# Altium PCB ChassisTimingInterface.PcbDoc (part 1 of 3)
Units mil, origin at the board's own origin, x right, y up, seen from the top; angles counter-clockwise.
Board outline 3400 x 6000 mil, 8 copper layers (Top Layer, GND, VDD, Mid-Layer 1, VCCAUX, Mid-Layer 2, MidLayer3, Bottom Layer), stack 62.1 mil thick; 229 components, 254 nets, 1249 pads, 708 vias.
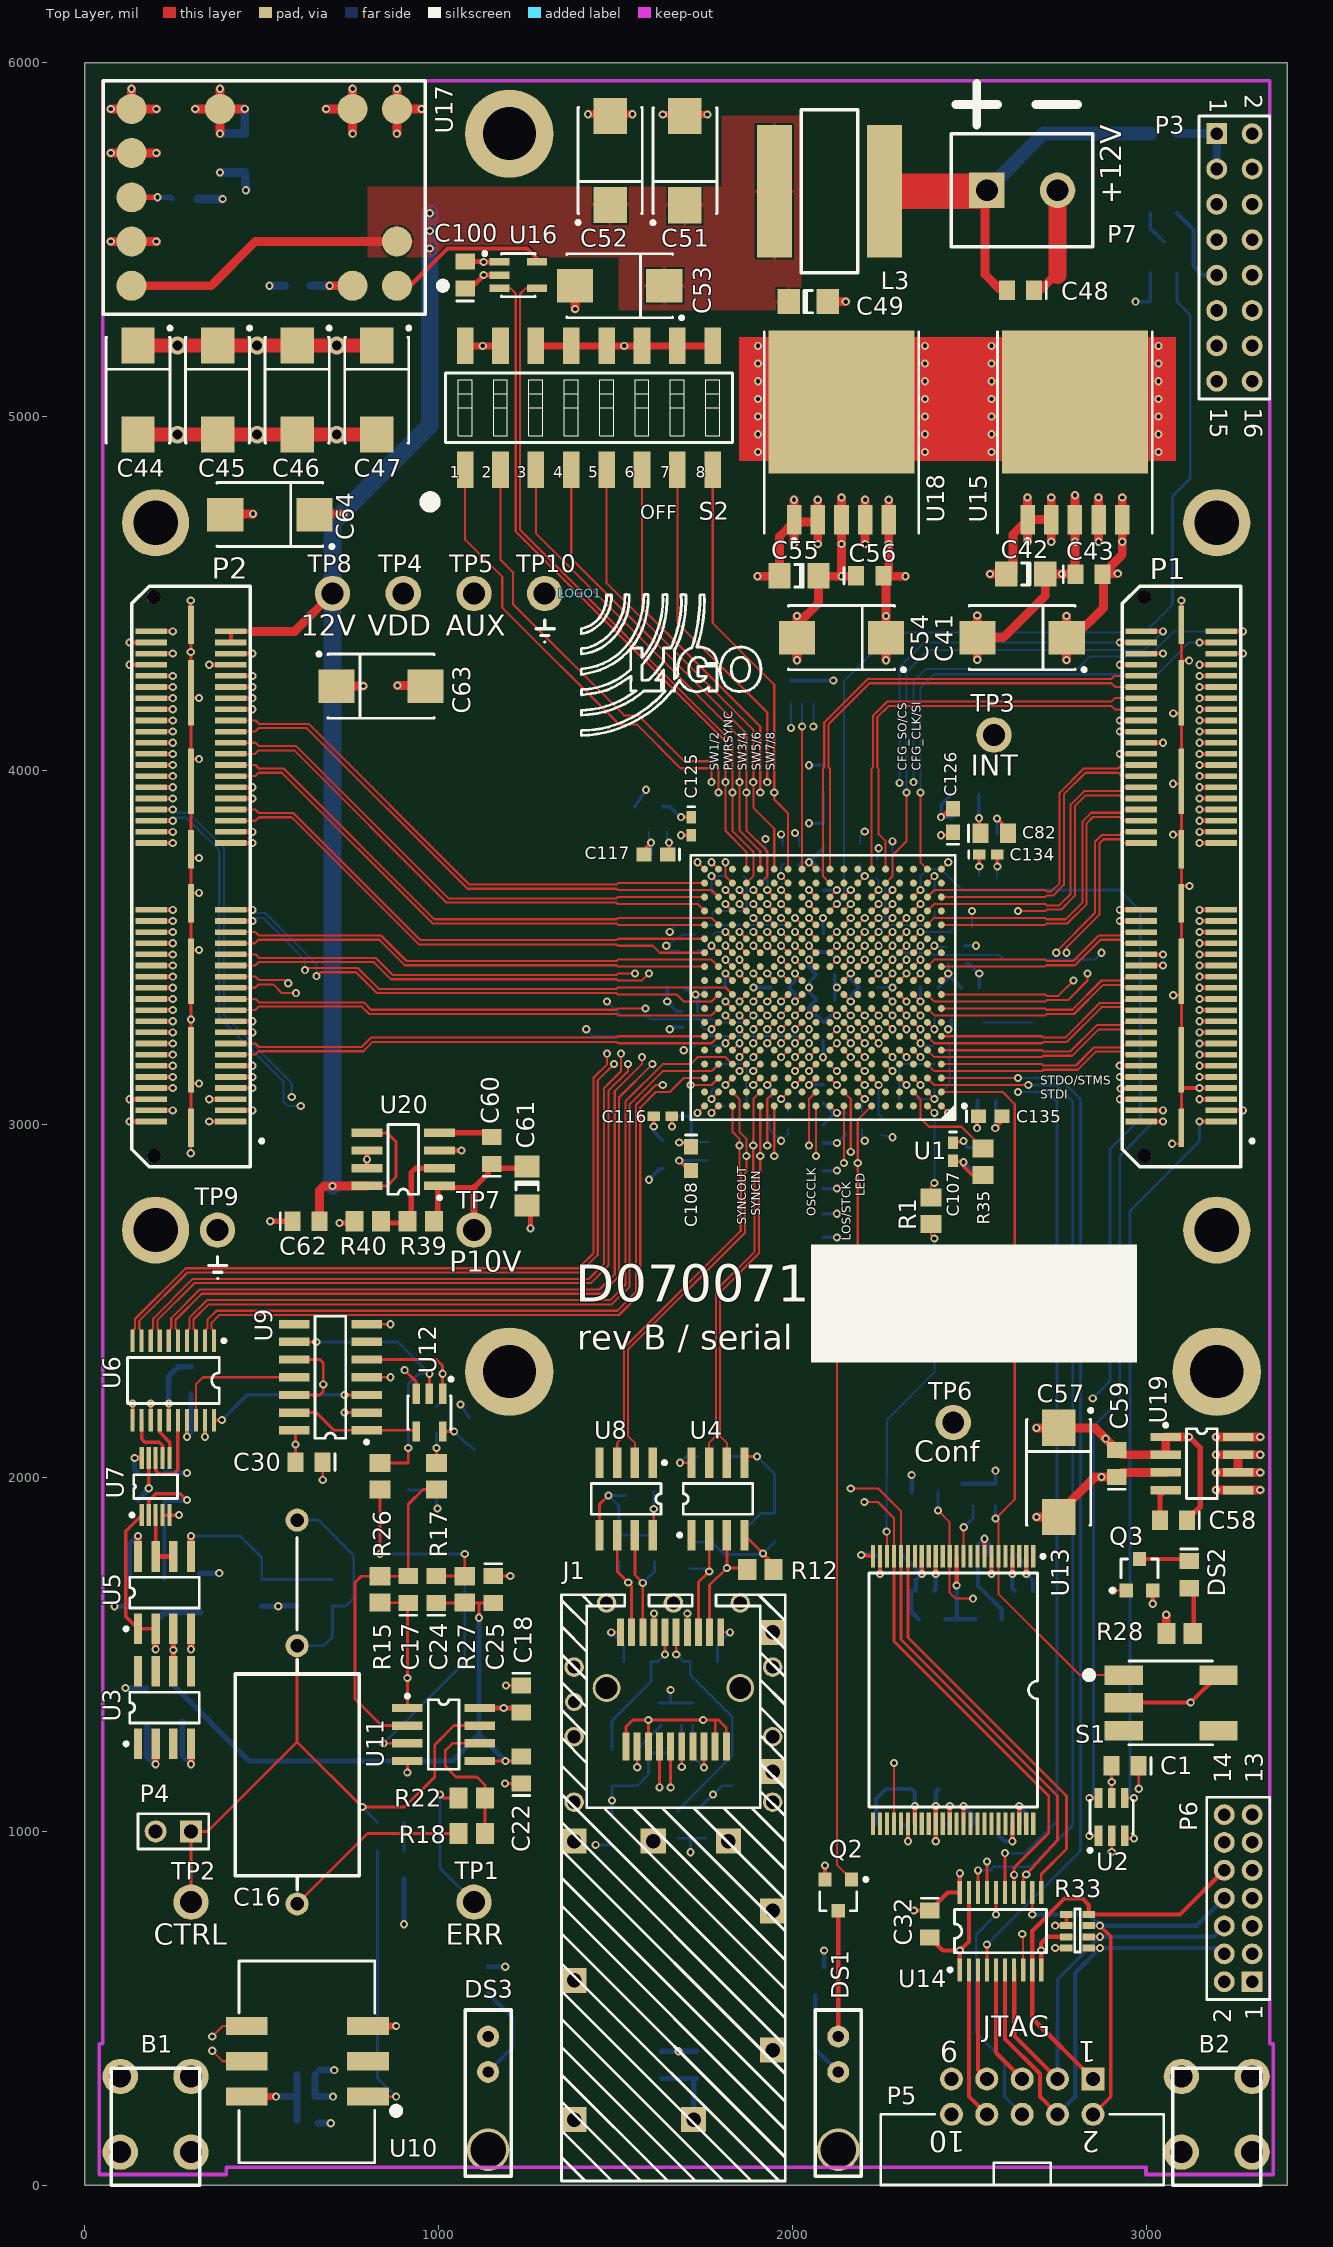
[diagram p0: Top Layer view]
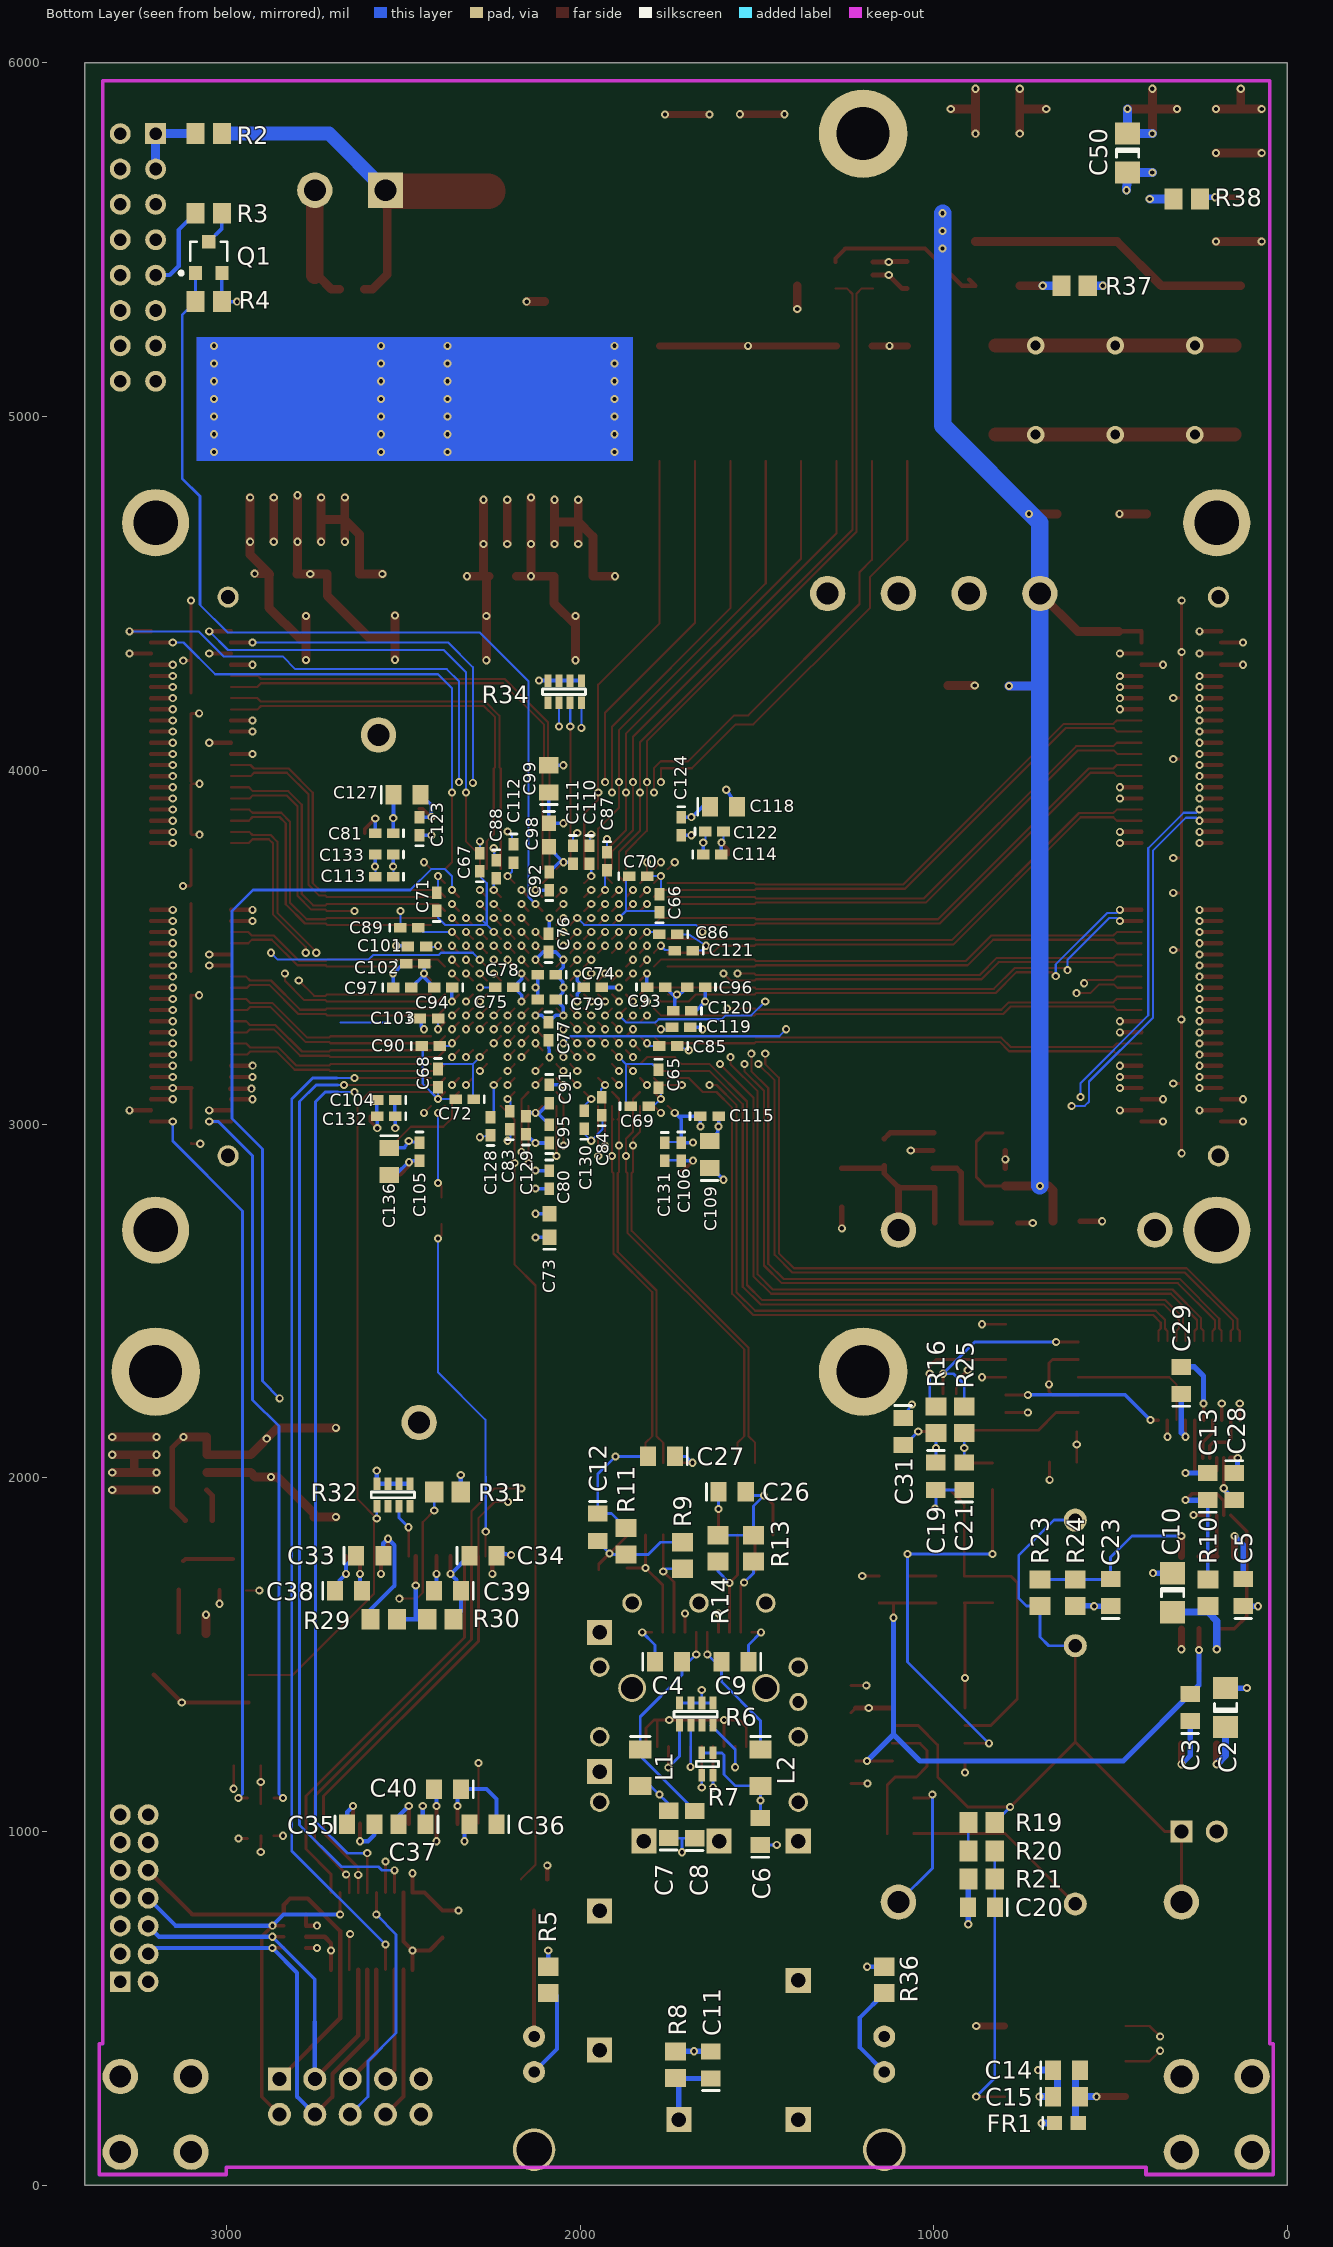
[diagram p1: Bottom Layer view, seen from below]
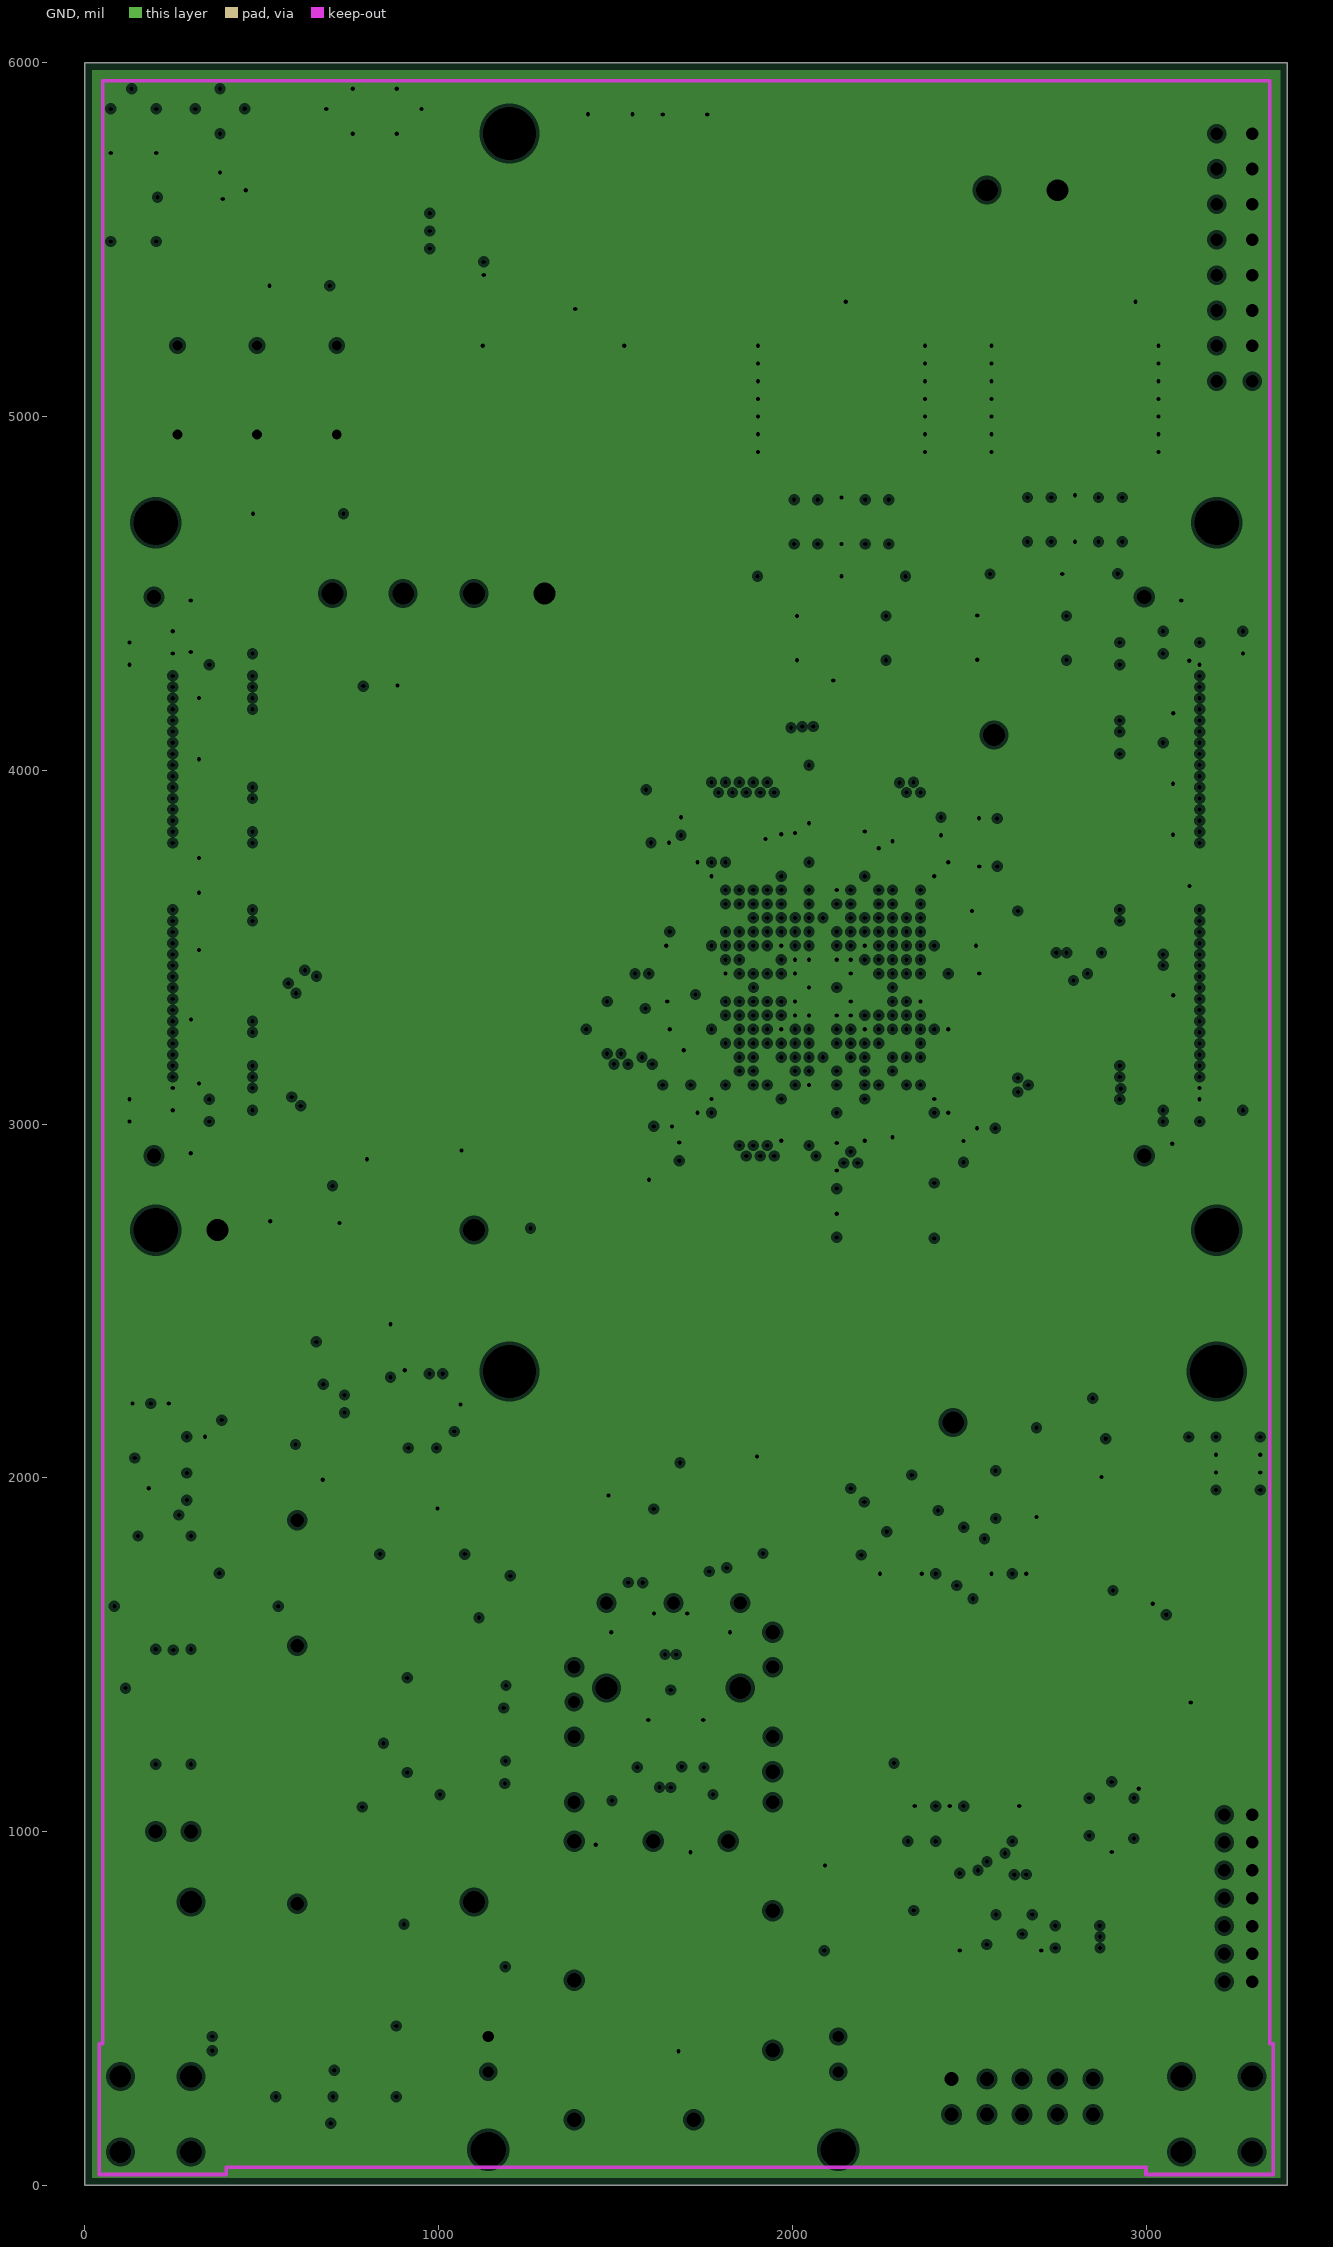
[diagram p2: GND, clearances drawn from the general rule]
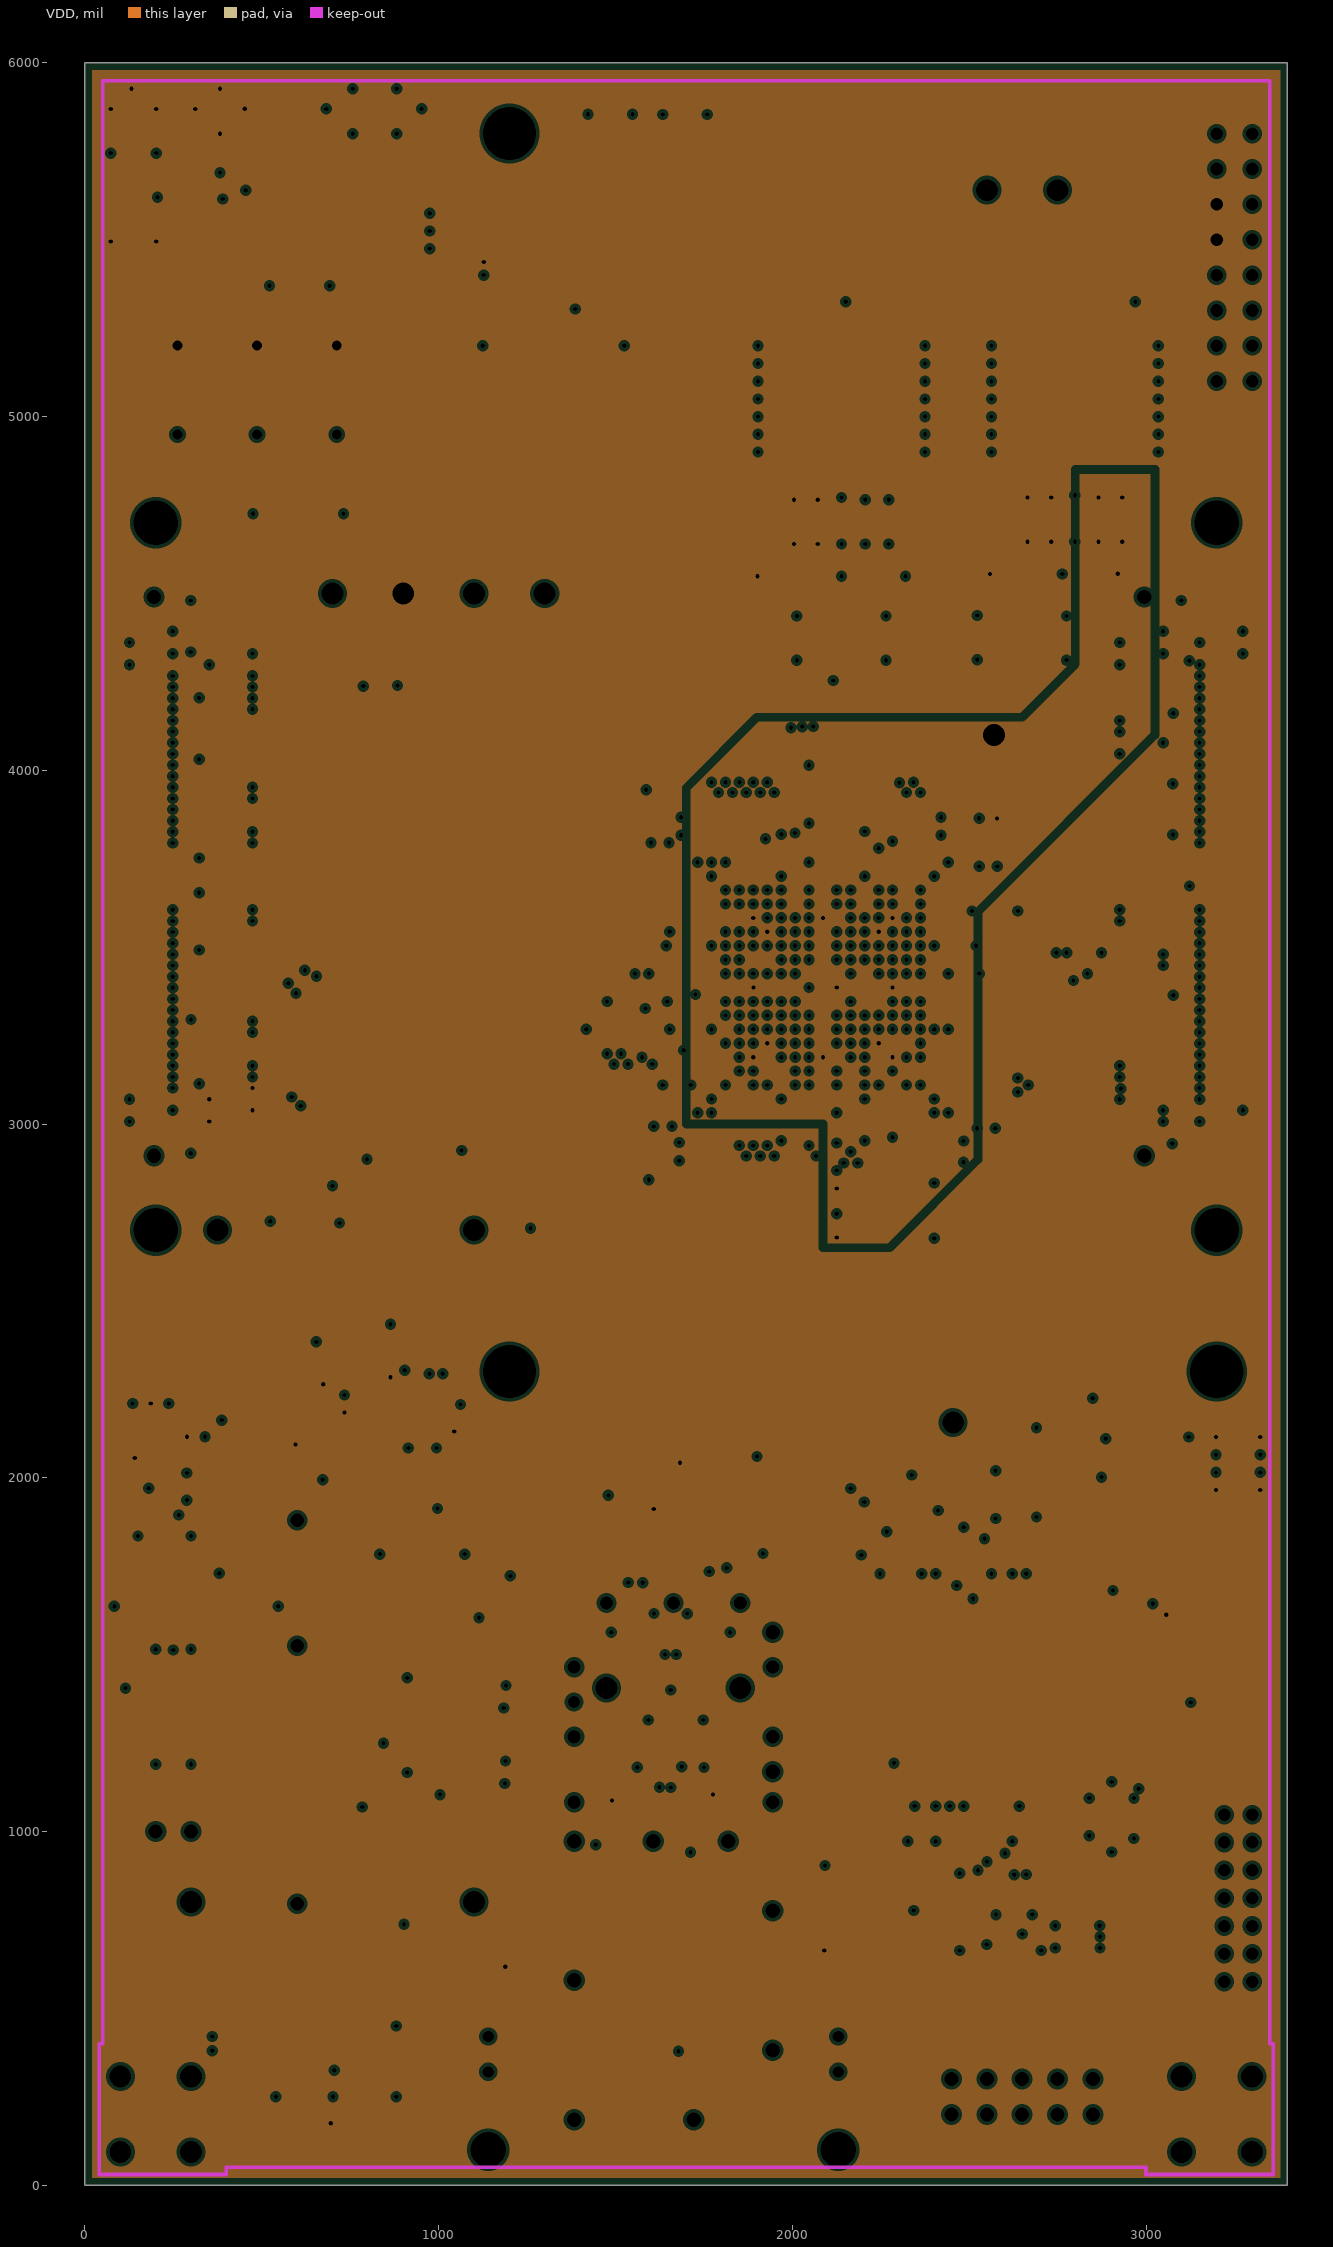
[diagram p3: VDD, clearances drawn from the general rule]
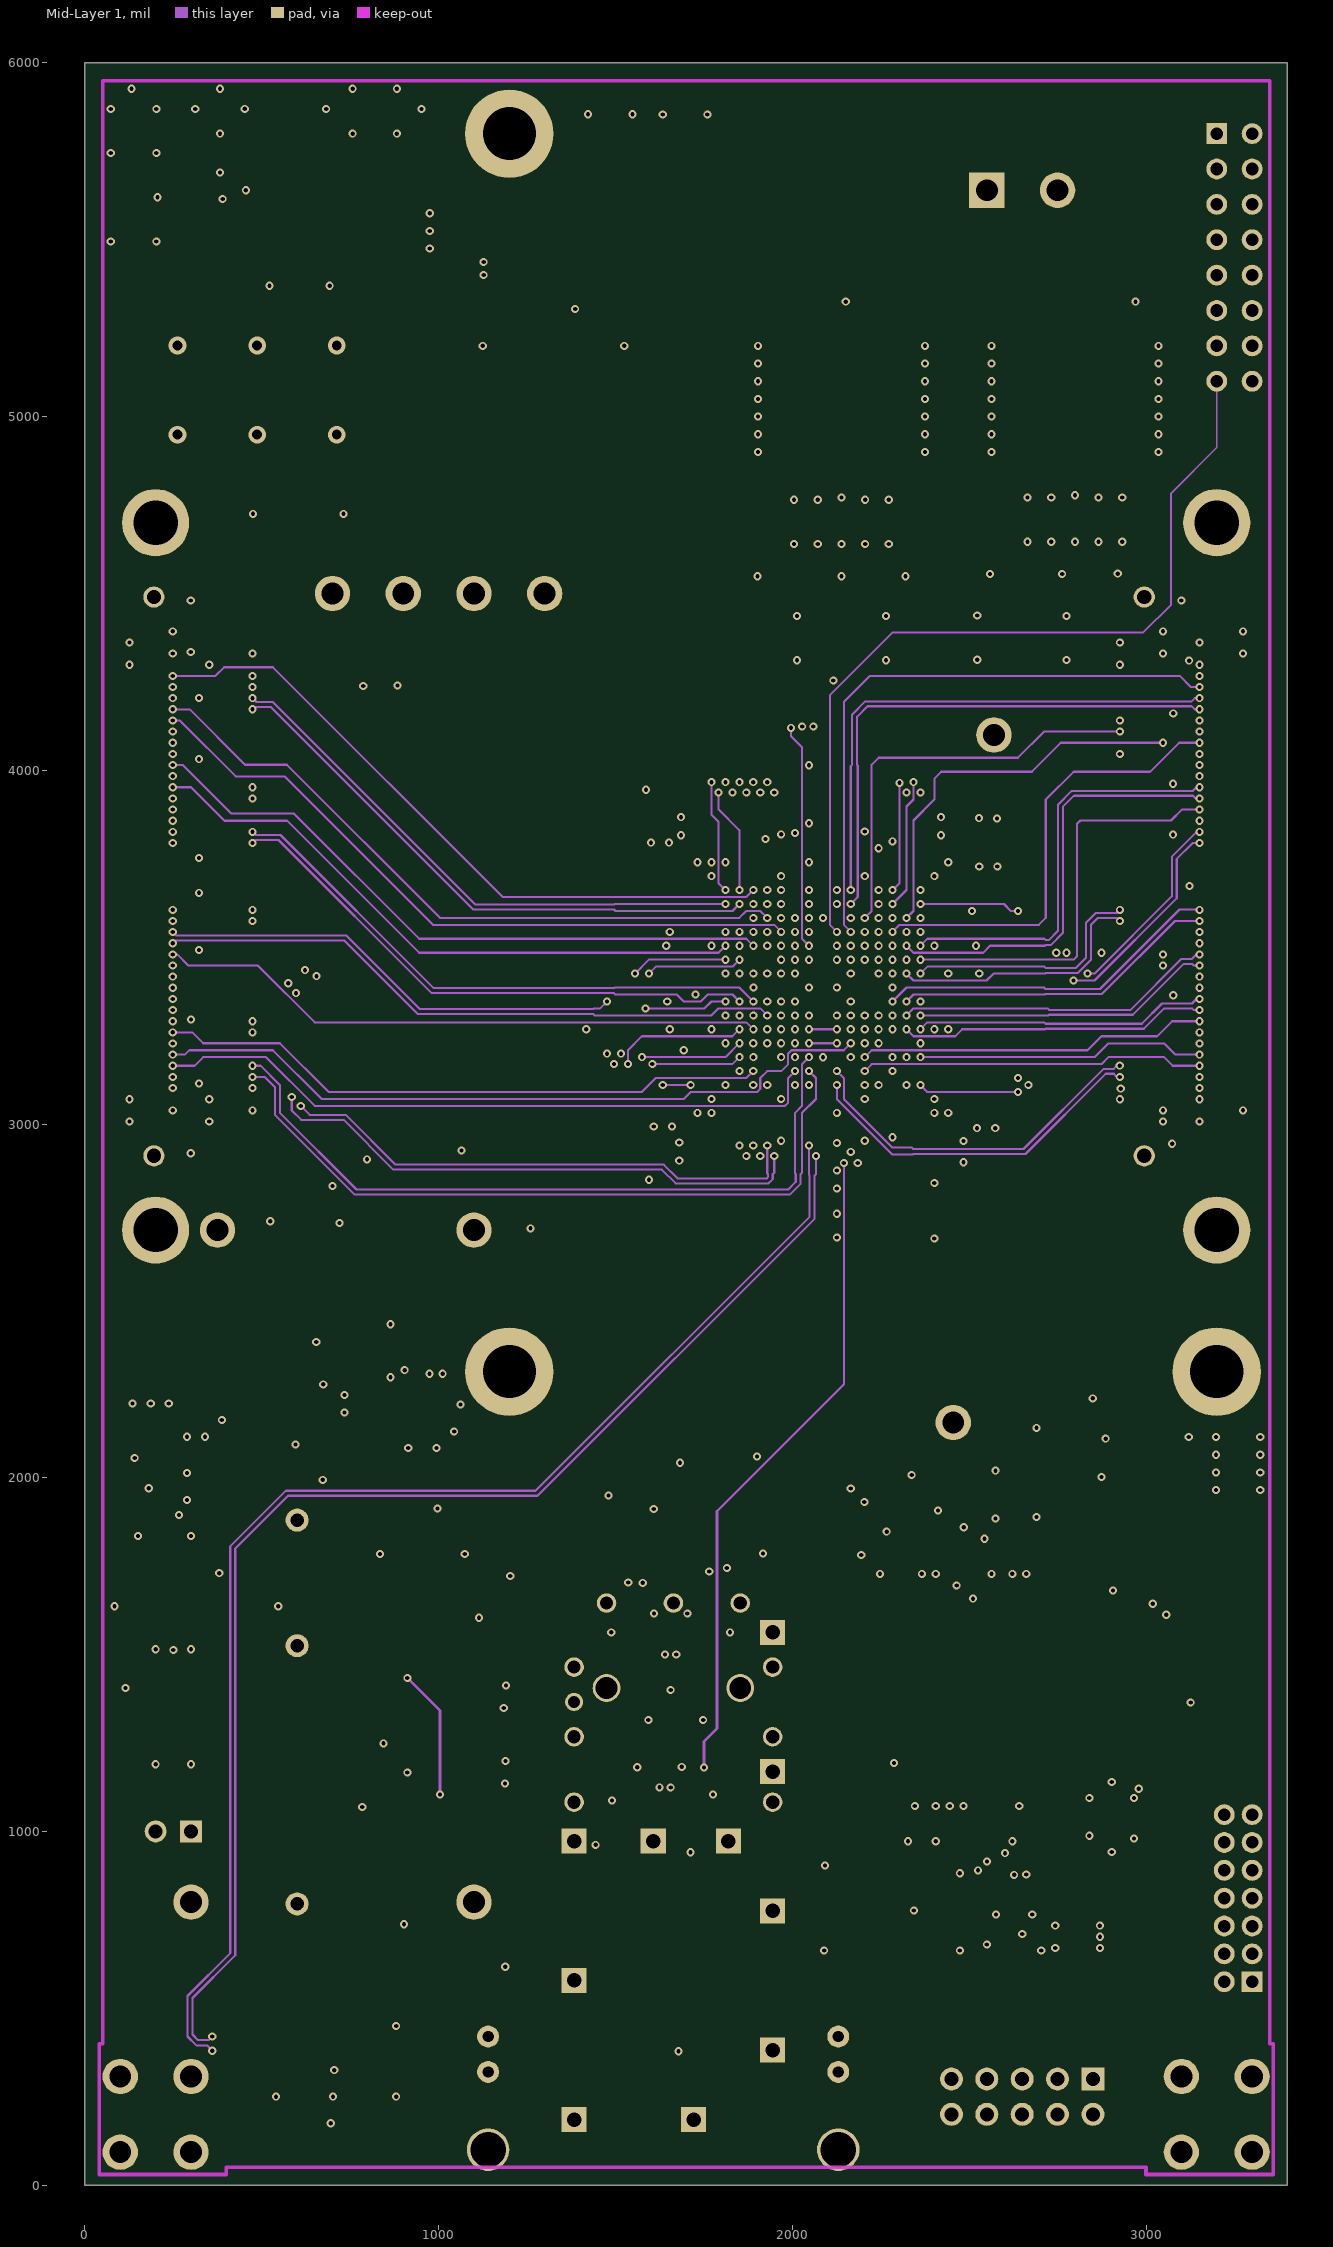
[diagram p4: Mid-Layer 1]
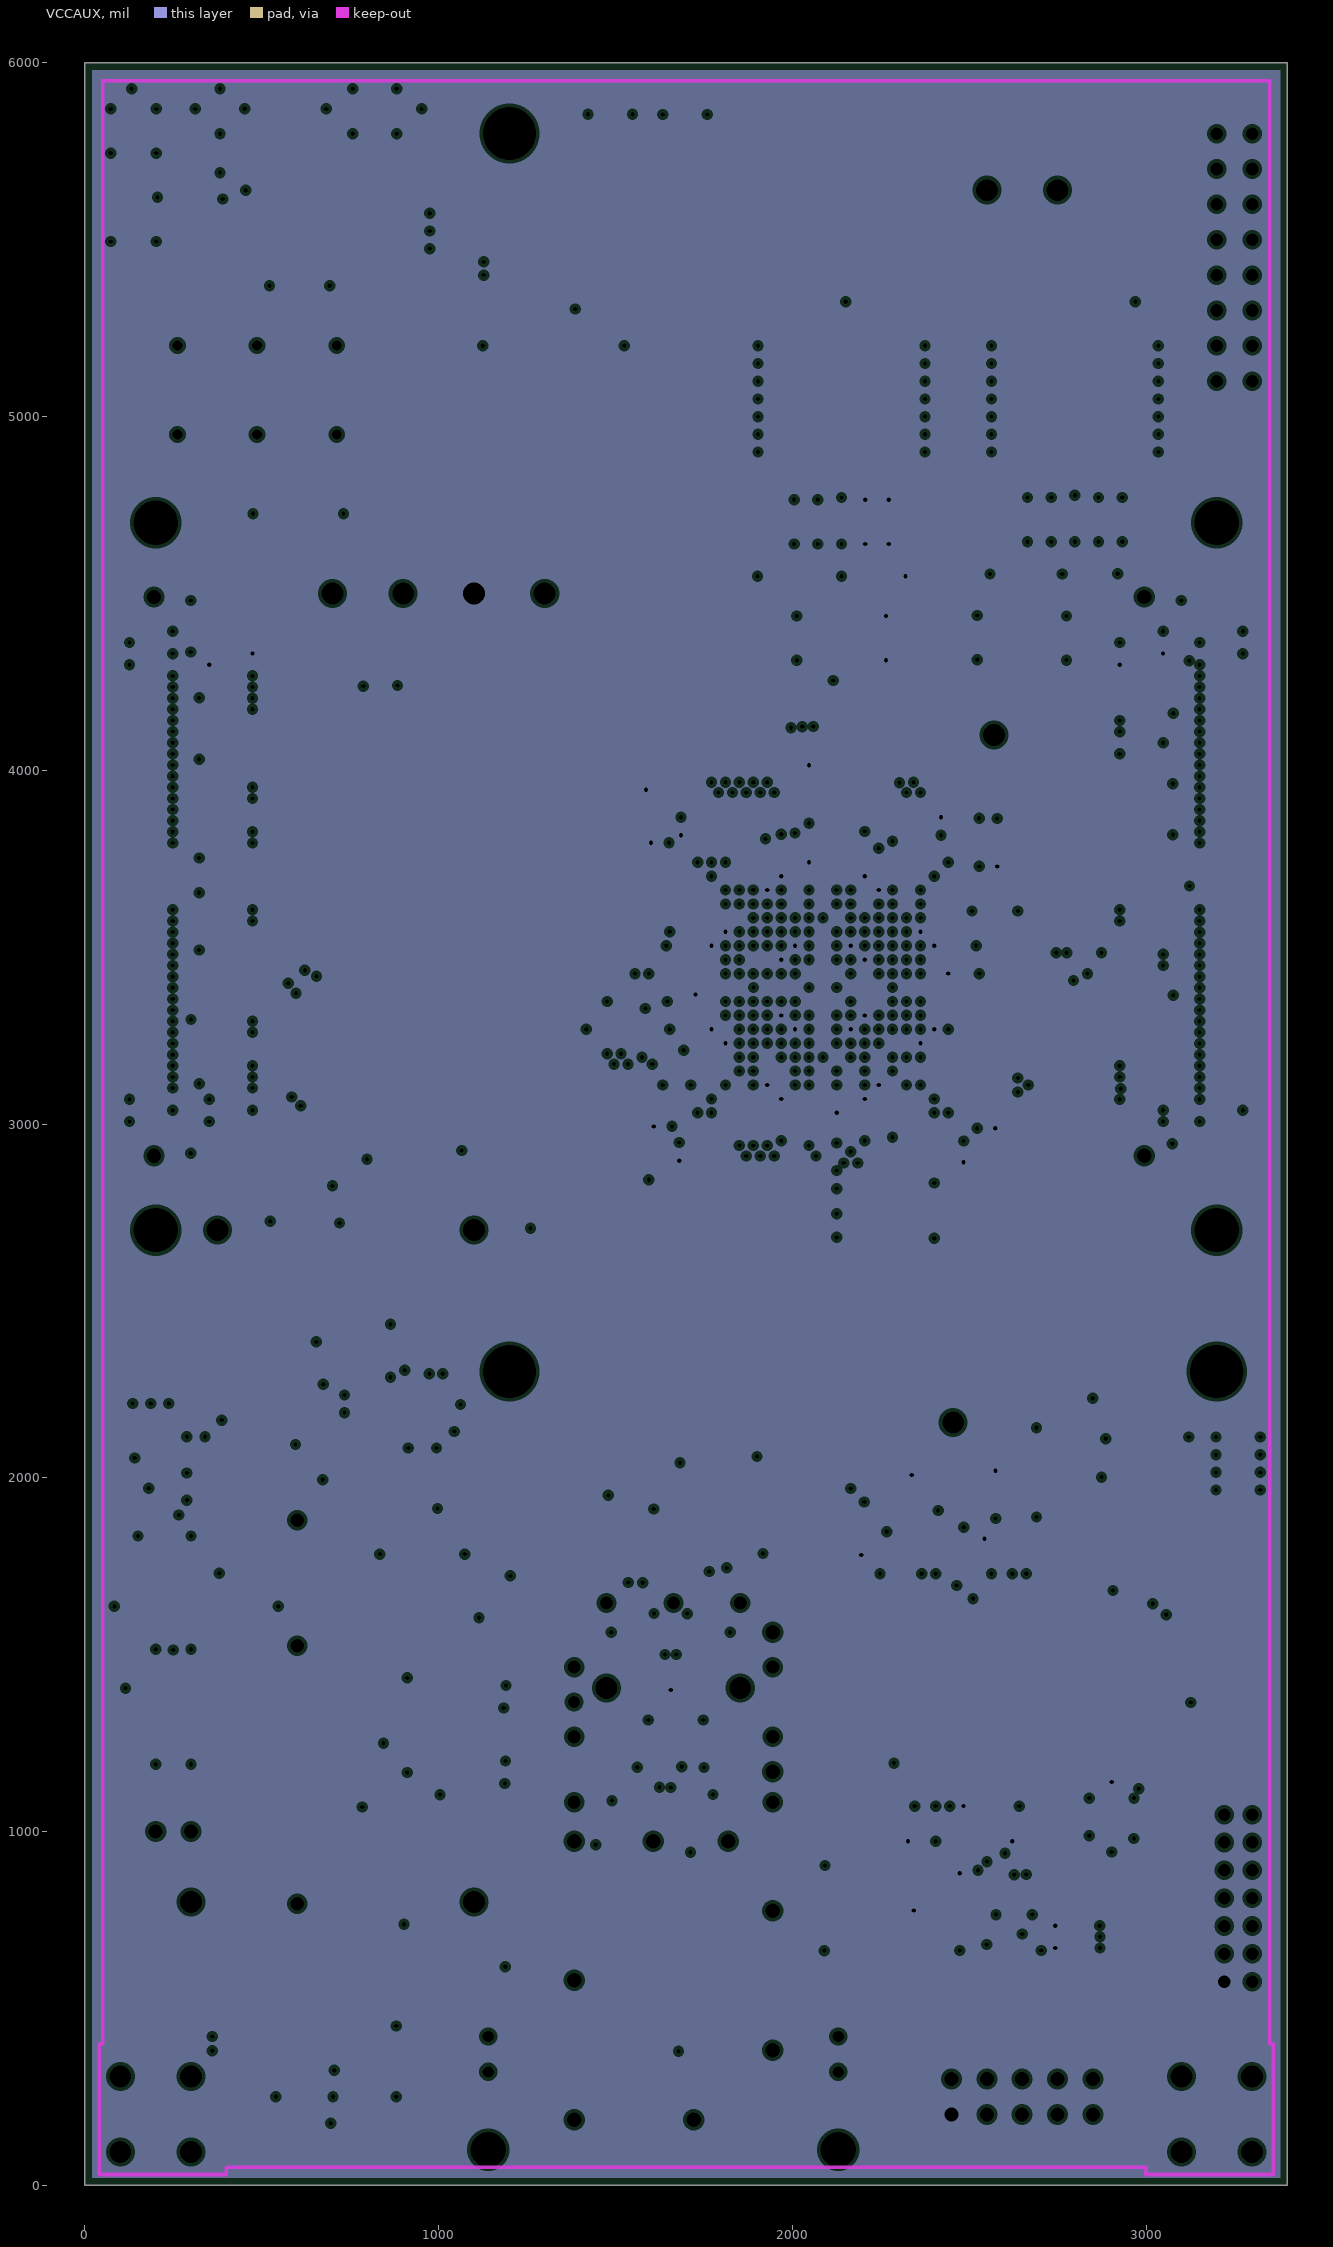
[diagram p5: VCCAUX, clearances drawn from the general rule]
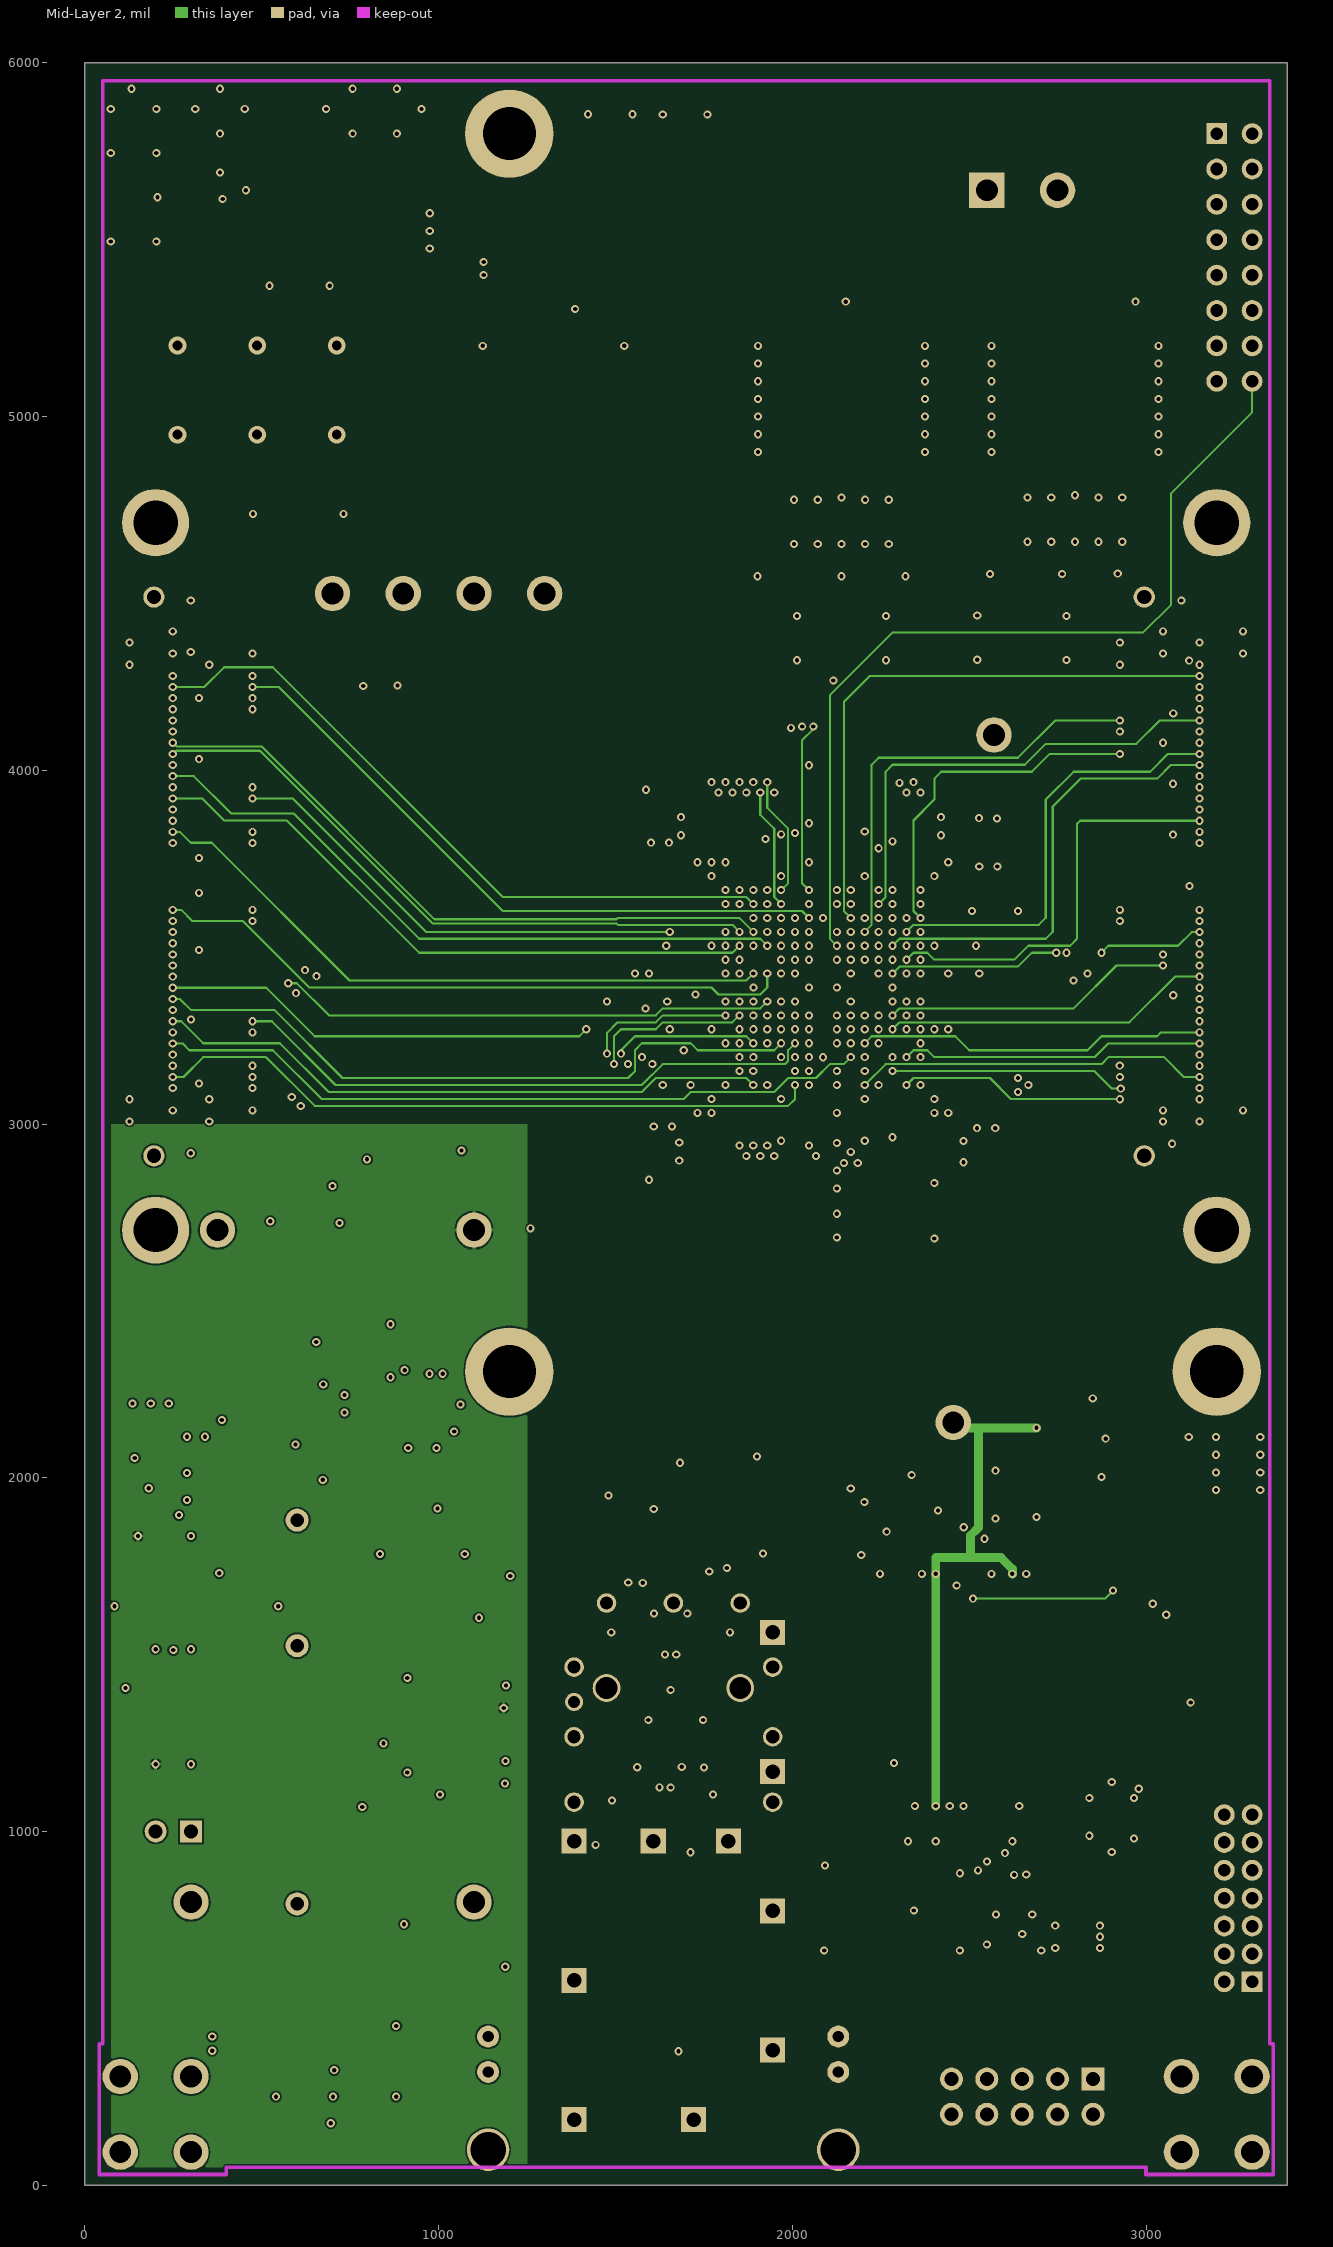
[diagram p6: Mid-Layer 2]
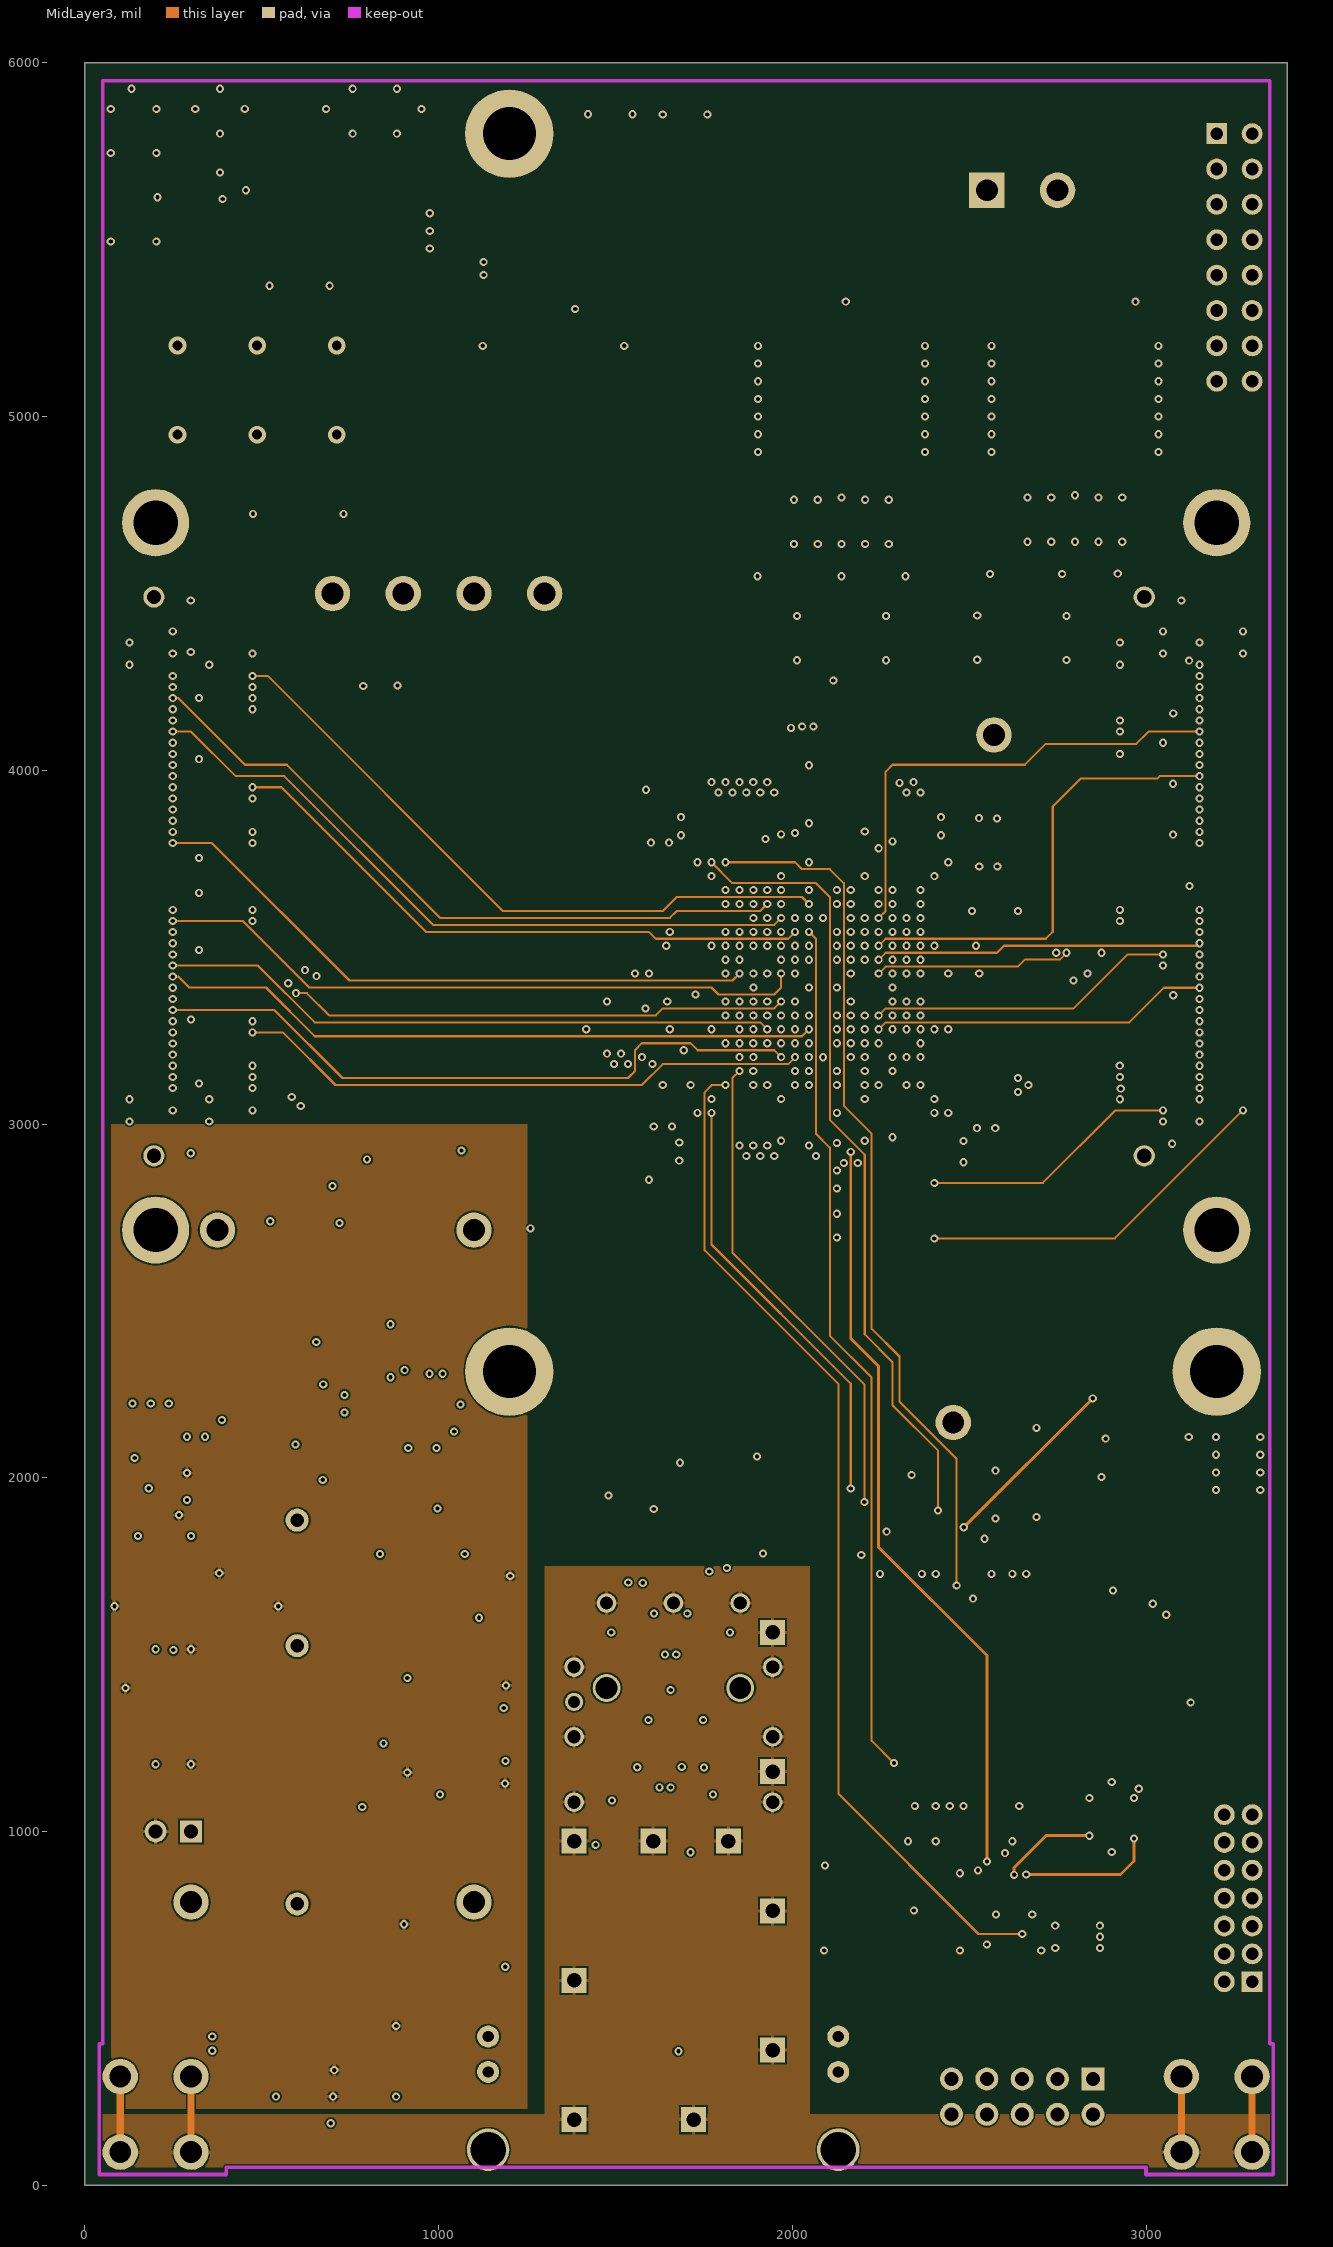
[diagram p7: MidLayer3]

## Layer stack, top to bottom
Top Layer: signal copper 1.4
Dielectric: prepreg 5.6, FR-4, Dk 4.2
GND: plane copper 1.4, net GND
Dielectric: core 9.5, FR-4, Dk 4.2
VDD: plane copper 1.4, net (Multiple Nets)
Dielectric: prepreg 5.6, FR-4, Dk 4.2
Mid-Layer 1: signal copper 1.4
Dielectric: core 9.5, FR-4, Dk 4.2
VCCAUX: plane copper 1.4, net VCCAUX
Dielectric: prepreg 5.6, FR-4, Dk 4.2
Mid-Layer 2: signal copper 1.4
Dielectric: core 9.5, FR-4, Dk 4.2
MidLayer3: signal copper 1.4
Dielectric: prepreg 5.6, FR-4, Dk 4.2
Bottom Layer: signal copper 1.4

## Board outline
0,0 0,6000 3400,6000 3400,0

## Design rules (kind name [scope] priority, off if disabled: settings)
Clearance Clearance_1 [All] p1: gap=5
ComponentClearance ComponentClearance_B2P4 [(InComponent('B2')) vs (InComponent('P5'))] p1: gap=-25 collisioncheckmode=0 verticalgap=25
ComponentClearance [All] p2: gap=10 collisioncheckmode=3 verticalgap=10
DiffPairsRouting [All] p1: maxlimit=10 minlimit=6 mostfreqgap=10 toplayer_prefgap=6 midlayer1_mingap=8 midlayer1_prefgap=8 midlayer2_prefgap=6 midlayer3_prefgap=6 bottomlayer_mingap=10 maxuncoupledlength=500
HoleSize [All] p1: absolutevalues=TRUE maxlimit=250 minlimit=1 maxpercent=80.000 minpercent=20.000
PlaneClearance [All] p1: clearance=10
PlaneConnect [All] p1: planeconnectstyle=Relief reliefexpansion=10 reliefentries=4 reliefconductorwidth=10 reliefairgap=10
PolygonConnect [All] p1: connectstyle=Relief reliefconductorwidth=10 reliefentries=4 polygonreliefangle="90 Angle"
RoomDefinition FPGA [InComponentClass('FPGA')] p1: confinementstyle=ConfineIn formatcopy=TRUE lockcomponents=FALSE outline -2000,-3000 0,-3000 0,-2000 -2000,-2000
RoutingLayers [All] p1: top layer_v5=TRUE mid layer 1_v5=TRUE mid layer 2_v5=TRUE mid layer 3_v5=FALSE bottom layer_v5=TRUE
RoutingVias [All] p1: holewidth=12 width=23 viastyle="Through Hole" minholewidth=12 minwidth=23 maxholewidth=28 maxwidth=50
ShortCircuit AGND [InNet('AGND') vs InNet('GND')] p1: allowed=TRUE
ShortCircuit [All] p2: allowed=FALSE
SolderMaskExpansion [All] p1: expansion=4
TestPointUsage [All] p1: valid=0 allowmultiple=FALSE
Testpoint [All] p1: side=15 testpointundercomponent=TRUE minsize=40 maxsize=100 preferedsize=60 minholesize=0 maxholesize=40 preferedholesize=32 testpointgrid=1 style=1023 order=0-112345678
Width [All] p1: maxlimit=100 minlimit=5 preferedwidth=5
12 further rules are at their usual default settings.

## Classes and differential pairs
component class FPGA: U1_B
component class ChassisTimingInterface1: C1 H1 H2 H3 H4 H5 H6 H7 H8 H9 H10 H11 H12 H13 H14 H15 H16 H17 H18 H19 H20 LOGO1 P1 P2 P3 Q1 R1 R2 R3 R4 U2
net class SW[10..1]: SW1 SW2 SW3 SW4 SW5 SW6 SW7 SW8 SW9 SW10
component class FIB: B1 B2 C2 C3 C4 C5 C6 C7 C8 C9 C10 C11 C12 C13 C14 C15 C16 C17 C18 C19 C20 C21 C22 C23 C24 C25 C26 C27 C28 C29 C30 C31 DS1 FR1 J1 L1 L2 LOGO2 P4 Q2 R5 R6 R7 R8 R9 R10 R11 R12 R13 R14 R15 R16 R17 R18 R19 R20 R21 R22 R23 R24 R25 R26 R27 TP1 TP2 U3 U4 U5 U6 U7 U8 U9 U10 U11 U12
component class PRG: C32 C33 C34 C35 C36 C37 C38 C39 C40 DS2 LOGO3 P5 P6 Q3 R28 R29 R30 R31 R32 R33 R34 R35 S1 S2 U13 U14
component class PWR: C41 C42 C43 C44 C45 C46 C47 C48 C49 C50 C51 C52 C53 C54 C55 C56 C57 C58 C59 C60 C61 C62 C63 C64 C65 C66 C67 C68 C69 C70 C71 C72 C73 C74 C75 C76 C77 C78 C79 C80 C81 C82 C83 C84 C85 C86 C87 C88 C89 C90 C91 C92 C93 C94 C95 C96 C97 C98 C99 C100 C101 C102 C103 C104 C105 C106 C107 C108 C109 C110 C111 C112 C113 C114 C115 C116 C117 C118 C119 C120 C121 C122 C123 C124 C125 C126 C127 C128 C129 C130 C131 C132 C133 C134 C135 C136 C194 DS3 L3 LOGO4 P7 R36 R37 R38 R39 R40 TP3 TP4 TP5 TP6 TP7 TP8 TP9 TP10 U15 U16 U17 U18 U19 U20
component class U_FPGA_U1_Auto: U1
differential pair S49_64.S64: +S49_64.S64_P -S49_64.S64_N
differential pair S49_64.S63: +S49_64.S63_P -S49_64.S63_N
differential pair S49_64.S62: +S49_64.S62_P -S49_64.S62_N
differential pair S49_64.S61: +S49_64.S61_P -S49_64.S61_N
differential pair S49_64.S60: +S49_64.S60_P -S49_64.S60_N
differential pair S49_64.S59: +S49_64.S59_P -S49_64.S59_N
differential pair S49_64.S58: +S49_64.S58_P -S49_64.S58_N
differential pair S49_64.S57: +S49_64.S57_P -S49_64.S57_N
differential pair S49_64.S56: +S49_64.S56_P -S49_64.S56_N
differential pair S49_64.S55: +S49_64.S55_P -S49_64.S55_N
differential pair S49_64.S54: +S49_64.S54_P -S49_64.S54_N
differential pair S49_64.S53: +S49_64.S53_P -S49_64.S53_N
differential pair S49_64.S52: +S49_64.S52_P -S49_64.S52_N
differential pair S49_64.S51: +S49_64.S51_P -S49_64.S51_N
differential pair S49_64.S50: +S49_64.S50_P -S49_64.S50_N
differential pair S49_64.S49: +S49_64.S49_P -S49_64.S49_N
differential pair S33_48.S48: +S33_48.S48_P -S33_48.S48_N
differential pair S33_48.S47: +S33_48.S47_P -S33_48.S47_N
differential pair S33_48.S46: +S33_48.S46_P -S33_48.S46_N
differential pair S33_48.S45: +S33_48.S45_P -S33_48.S45_N
differential pair S33_48.S44: +S33_48.S44_P -S33_48.S44_N
differential pair S33_48.S43: +S33_48.S43_P -S33_48.S43_N
differential pair S33_48.S42: +S33_48.S42_P -S33_48.S42_N
differential pair S33_48.S41: +S33_48.S41_P -S33_48.S41_N
differential pair S33_48.S40: +S33_48.S40_P -S33_48.S40_N
differential pair S33_48.S39: +S33_48.S39_P -S33_48.S39_N
differential pair S33_48.S38: +S33_48.S38_P -S33_48.S38_N
differential pair S33_48.S37: +S33_48.S37_P -S33_48.S37_N
differential pair S33_48.S36: +S33_48.S36_P -S33_48.S36_N
differential pair S33_48.S35: +S33_48.S35_P -S33_48.S35_N
differential pair S33_48.S34: +S33_48.S34_P -S33_48.S34_N
differential pair S33_48.S33: +S33_48.S33_P -S33_48.S33_N
differential pair S17_32.S32: +S17_32.S32_P -S17_32.S32_N
differential pair S17_32.S31: +S17_32.S31_P -S17_32.S31_N
differential pair S17_32.S30: +S17_32.S30_P -S17_32.S30_N
differential pair S17_32.S29: +S17_32.S29_P -S17_32.S29_N
differential pair S17_32.S28: +S17_32.S28_P -S17_32.S28_N
differential pair S17_32.S27: +S17_32.S27_P -S17_32.S27_N
differential pair S17_32.S26: +S17_32.S26_P -S17_32.S26_N
differential pair S17_32.S25: +S17_32.S25_P -S17_32.S25_N
differential pair S17_32.S24: +S17_32.S24_P -S17_32.S24_N
differential pair S17_32.S23: +S17_32.S23_P -S17_32.S23_N
differential pair S17_32.S22: +S17_32.S22_P -S17_32.S22_N
differential pair S17_32.S21: +S17_32.S21_P -S17_32.S21_N
differential pair S17_32.S20: +S17_32.S20_P -S17_32.S20_N
differential pair S17_32.S19: +S17_32.S19_P -S17_32.S19_N
differential pair S17_32.S18: +S17_32.S18_P -S17_32.S18_N
differential pair S17_32.S17: +S17_32.S17_P -S17_32.S17_N
differential pair S1_16.S16: +S1_16.S16_P -S1_16.S16_N
differential pair S1_16.S15: +S1_16.S15_P -S1_16.S15_N
differential pair S1_16.S14: +S1_16.S14_P -S1_16.S14_N
differential pair S1_16.S13: +S1_16.S13_P -S1_16.S13_N
differential pair S1_16.S12: +S1_16.S12_P -S1_16.S12_N
differential pair S1_16.S11: +S1_16.S11_P -S1_16.S11_N
differential pair S1_16.S10: +S1_16.S10_P -S1_16.S10_N
differential pair S1_16.S9: +S1_16.S9_P -S1_16.S9_N
differential pair AIN: +AIN_P -AIN_N
differential pair ACNV: +ACNV_P -ACNV_N
differential pair ACLK: +ACLK_P -ACLK_N
differential pair SYNCOUT: +SYNCOUT_P -SYNCOUT_N
differential pair SYNC: +SYNC_P -SYNC_N
differential pair S4: +S1_16.S4_P -S1_16.S4_N
differential pair CNTROUT: +CNTROUT_P -CNTROUT_N
differential pair OSCCLK: +OSCCLK_P -OSCCLK_N
differential pair PWRSYNC: +PWRSYNC_P -PWRSYNC_N
differential pair S1: +S1_16.S1_P -S1_16.S1_N
differential pair S2: +S1_16.S2_P -S1_16.S2_N
differential pair S3: +S1_16.S3_P -S1_16.S3_N
differential pair S5: +S1_16.S5_P -S1_16.S5_N
differential pair S6: +S1_16.S6_P -S1_16.S6_N
differential pair S7: +S1_16.S7_P -S1_16.S7_N
differential pair S8: +S1_16.S8_P -S1_16.S8_N
differential pair SYNCIN: +SYNCIN_P -SYNCIN_N
differential pair SYNCLK: +SYNCLK_P -SYNCLK_N

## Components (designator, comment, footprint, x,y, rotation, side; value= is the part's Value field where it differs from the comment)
B1 "Bracket" Bracket-RA_7774 200,200 r180 top locked
B2 "Bracket" Bracket-RA_7774 3200,200 r180 top locked
C1 "100n" CC2013-0805 2941,1185 r180 top
C2 "10u" CC3216-1206 175,1350 r90 bottom
C3 "1u" CC2013-0805 275,1350 r90 bottom
C4 "100n" CC2013-0805 1750,1480 r180 bottom
C5 "1u" CC2013-0805 125,1675 r90 bottom
C6 "100n" CC2013-0805 1490,1000 r90 bottom
C7 "10u" CC2013-0805 1750,1020 r90 bottom
C8 "10u" CC2013-0805 1676,1019 r90 bottom
C9 "100n" CC2013-0805 1562,1480 r0 bottom
C10 "10u" CC3216-1206 325,1675 r270 bottom
C11 "100n" CC2013-0805 1630,340 r90 bottom
C12 "10n" CC2013-0805 1950,1860 r270 bottom
C13 "1u" CC2013-0805 225,1975 r90 bottom
C14 "10u" CC2013-0805 625,325 r180 bottom
C15 "100n" CC2013-0805 625,250 r180 bottom
C16 "470n" CA053035 600,795 r90 top
C17 "NL" CC2013-0805 914,1684 r90 top
C18 "100n" CC2013-0805 1234,1374 r270 top
C19 "1n" CC2013-0805 994,2004 r270 bottom
C20 "1n" CC2013-0805 865,785 r0 bottom
C21 "1n" CC2013-0805 914,2004 r90 bottom
C22 "100n" CC2013-0805 1234,1174 r90 top
C23 "100n" CC2013-0805 500,1675 r90 bottom
C24 "NL" CC2013-0805 994,1684 r90 top
C25 "100n" CC2013-0805 1154,1684 r270 top
C26 "100n" CC2013-0805 1570,1960 r180 bottom
C27 "100n" CC2013-0805 1770,2060 r0 bottom
C28 "100n" CC2013-0805 150,1975 r270 bottom
C29 "100n" CC2013-0805 300,2275 r90 bottom
C30 "100n" CC2013-0805 634.02,2044.02 r180 top
C31 "100n" CC2013-0805 1087,2131 r270 bottom
C32 "100n" CC2013-0805 2388.78,737.99 r270 top
C33 "100n" CC2013-0805 2594.8,1779.84 r180 bottom
C34 "100n" CC2013-0805 2274.8,1779.84 r180 bottom
C35 "100n" CC2013-0805 2620,1020 r180 bottom
C36 "100n" CC2013-0805 2274.8,1019.84 r0 bottom
C37 "100n" CC2013-0805 2474.8,1019.84 r0 bottom
C38 "100n" CC2013-0805 2654.8,1679.84 r180 bottom
C39 "100n" CC2013-0805 2374.8,1679.84 r0 bottom
C40 "100n" CC2013-0805 2374.8,1119.84 r0 bottom
C41 "1m" TC7343-2917 2650,4375 r180 top
C42 "10u" CC3216-1206 2660,4555 r180 top
C43 "1u" CC2013-0805 2839,4554 r0 top
C44 "680u" TC7343-2917 150,5075 r270 top
C45 "680u" TC7343-2917 375,5075 r270 top
C46 "680u" TC7343-2917 600,5075 r270 top
C47 "680u" TC7343-2917 825,5075 r270 top
C48 "100n" CC2013-0805 2645,5357 r180 top
C49 "10u" CC3216-1206 2045,5325 r0 top
C50 "100u" CC3216-1206 452,5745 r270 bottom
C51 "68u" TC7343-2917 1696.49,5723.5 r90 top
C52 "68u" TC7343-2917 1485,5724 r90 top
C53 "68u" TC7343-2917 1512,5370 r180 top
C54 "1m" TC7343-2917 2139,4375 r180 top
C55 "10u" CC3216-1206 2019,4550 r180 top
C56 "1u" CC2013-0805 2219,4550 r0 top
C57 "1m" TC7343-2917 2753,2015 r270 top
C58 "10n" CC2013-0805 3078,1880 r180 top
C59 "1u" CC2013-0805 2918,2040 r90 top
C60 "10n" CC2013-0805 1150,2925 r90 top
C61 "10u" CC3216-1206 1250,2825 r270 top
C62 "100n" CC2013-0805 625,2725 r0 top
C63 "68u" TC7343-2917 837,4238 r0 top
C64 "68u" TC7343-2917 523,4723 r180 top
C65 "1n" CC1005-0402 1778.54,3127.94 r270 bottom
C66 "1n" CC1005-0402 1775.59,3624.01 r90 bottom
C67 "1n" CC1005-0402 2283.47,3740.15 r90 bottom
C68 "1n" CC1005-0402 2401.58,3129.91 r270 bottom
C69 "10n" CC1005-0402 1831.69,3050.19 r180 bottom
C70 "10n" CC1005-0402 1835.63,3700.78 r180 bottom
C71 "100n" CC1005-0402 2405.51,3627.94 r90 bottom
C72 "100n" CC1005-0402 2325.79,3069.87 r0 bottom
C73 "1u" CC1608-0603 2087.06,2712.88 r90 bottom
C74 "1n" CC1005-0402 1964.06,3386.88 r180 bottom
C75 "1n" CC1005-0402 2214.06,3386.88 r0 bottom
C76 "1n" CC1005-0402 2089.06,3511.88 r90 bottom
C77 "1n" CC1005-0402 2089.06,3261.88 r270 bottom
C78 "10n" CC1005-0402 2094.06,3421.88 r0 bottom
C79 "10n" CC1005-0402 2094.06,3351.88 r0 bottom
C80 "100n" CC1005-0402 2087.06,2842.88 r270 bottom
C81 "100n" CC1005-0402 2554.06,3821.88 r0 bottom
C82 "10u" CC2013-0805 2571.06,3821.88 r0 top
C83 "1n" CC1005-0402 2198.82,3010.82 r90 bottom
C84 "1n" CC1005-0402 1938.98,3050.19 r90 bottom
C85 "1n" CC1005-0402 1750.99,3220.46 r0 bottom
C86 "1n" CC1005-0402 1750.99,3536.41 r0 bottom
C87 "1n" CC1005-0402 1924.21,3743.1 r270 bottom
C88 "1n" CC1005-0402 2237.21,3720.46 r270 bottom
C89 "1n" CC1005-0402 2483.27,3555.11 r180 bottom
C90 "1n" CC1005-0402 2422.24,3220.46 r180 bottom
C91 "10n" CC1005-0402 2087.06,3084.88 r270 bottom
C92 "10n" CC1005-0402 2087.06,3686.88 r90 bottom
C93 "10n" CC1005-0402 1785.06,3386.88 r180 bottom
C94 "10n" CC1005-0402 2387.06,3385.88 r0 bottom
C95 "100n" CC1005-0402 2087.06,2971.88 r90 bottom
C96 "100n" CC1005-0402 1672.06,3386.88 r0 bottom
C97 "100n" CC1005-0402 2503.06,3385.88 r180 bottom
C98 "1u" CC1608-0603 2088.06,3816.88 r270 bottom
C99 "10u" CC2013-0805 2088.06,3975.88 r90 bottom
C100 "100n" CC2013-0805 1075,5400 r90 top
C101 "1n" CC1005-0402 2461,3502 r180 bottom
C102 "1n" CC1005-0402 2465.55,3452.75 r180 bottom
C103 "1n" CC1005-0402 2427.17,3298.22 r180 bottom
C104 "1n" CC1005-0402 2548.23,3067.9 r0 bottom
C105 "10n" CC1005-0402 2454.06,2921.88 r270 bottom
C106 "10n" CC1005-0402 1714.06,2921.88 r270 bottom
C107 "100n" CC1005-0402 2454.06,2921.88 r270 top
C108 "1u" CC1608-0603 1714.06,2901.88 r270 top
C109 "10u" CC2013-0805 1633.86,2913.38 r90 bottom
C110 "1n" CC1005-0402 1973.43,3760.82 r270 bottom
C111 "1n" CC1005-0402 2019.69,3760.82 r270 bottom
C112 "1n" CC1005-0402 2187.99,3764.76 r270 bottom
C113 "1n" CC1005-0402 2554.13,3698.81 r0 bottom
C114 "10n" CC1005-0402 1626.06,3761.88 r180 bottom
C115 "10n" CC1005-0402 1634.06,3021.88 r180 bottom
C116 "100n" CC1005-0402 1634.06,3021.88 r180 top
C117 "1u" CC1608-0603 1614.06,3761.88 r180 top
C118 "10u" CC2013-0805 1594.49,3897.63 r180 bottom
C119 "1n" CC1005-0402 1714.57,3273.61 r0 bottom
C120 "1n" CC1005-0402 1711.61,3319.87 r0 bottom
C121 "1n" CC1005-0402 1706.69,3490.15 r0 bottom
C122 "1n" CC1005-0402 1620.08,3826.76 r180 bottom
C123 "10n" CC1005-0402 2454.06,3841.88 r90 bottom
C124 "10n" CC1005-0402 1714.06,3841.88 r270 bottom
C125 "100n" CC1005-0402 1714.06,3841.88 r270 top
C126 "1u" CC1608-0603 2454.06,3857.88 r90 top
C127 "10u" CC2013-0805 2489.17,3931.09 r180 bottom
C128 "1n" CC1005-0402 2252.95,2994.09 r90 bottom
C129 "1n" CC1005-0402 2152.56,2996.05 r90 bottom
C130 "1n" CC1005-0402 1988.19,3011.8 r90 bottom
C131 "1n" CC1005-0402 1760.83,2921.25 r270 bottom
C132 "10n" CC1005-0402 2548.06,3021.88 r0 bottom
C133 "10n" CC1005-0402 2554.06,3761.88 r0 bottom
C134 "100n" CC1005-0402 2554.06,3761.88 r0 top
C135 "1u" CC1608-0603 2559.65,3021.88 r0 top
C136 "10u" CC2013-0805 2539.37,2893.69 r270 bottom
DS1 "LED" LED-2 2130,320 r0 top locked
DS2 "LED" LED-0805 3121.8,1725.84 r270 top
DS3 "LED" LED-2 1140,320 r0 top locked
FR1 "MPZ1608S221A" CL1608-0603 625,175 r180 bottom
J1 "AFBR-5710" MSA/SFP2x10 1530,1240 r90 top locked
L1 "1uH" CL2520-1008 1830,1180 r270 bottom
L2 "1uH" CL2520-1008 1490,1180 r270 bottom
L3 "560nH" MVR1251 2105,5637 r180 top
LOGO1 "LIGO logo" LIGO_LOGO 1400,4500 r0 top
P1 "QSE40" QSE040 3100,3700 r90 top locked
P2 "QSE40" QSE040 300,3700 r90 top locked
P3 "Header 8X2" HDR2X8 3200,5800 r270 top
P4 "Header 2" HDR1X2 300,1000 r180 top
P5 "09 18 510 6323" 918510x323 2650,200 r180 top locked
P6 "2mm Header 2x7" 2MM_HDR2X7 3300,575 r90 top
P7 "TBlock_5.08_2" TBLOCK-5.08-2 2650,5640 r0 top
Q1 "FDV301N" SO-G3/C2.25 3050,5450 r180 bottom
Q2 "FDV301N" SO-G3/C2.25 2130,820 r180 top
Q3 "FDV301N" SO-G3/C2.25 2981.8,1725.84 r0 top
R1 "0" CR2012-0805 2392,2755 r270 top
R2 "0" CR2012-0805 3050,5800 r180 bottom
R3 "10" CR2012-0805 3050,5575 r180 bottom
R4 "4.7K" CR2012-0805 3050,5325 r0 bottom
R5 "100" CR2012-0805 2090,580 r90 bottom
R6 "Resistor Array" RES8-0.8 1718.5,1300 r90 bottom
R7 "Resistor Array" RES4-0.8 1656,1159 r90 bottom
R8 "10" CR2012-0805 1730,340 r90 bottom
R9 "49.9" CR2012-0805 1710,1780 r270 bottom
R10 "10" CR2012-0805 225,1675 r270 bottom
R11 "22K" CR2012-0805 1870,1820 r90 bottom
R12 "49.9" CR2012-0805 1910,1740 r180 top
R13 "392" CR2012-0805 1510,1800 r270 bottom
R14 "392" CR2012-0805 1610,1800 r90 bottom
R15 "30K" CR2012-0805 834,1684 r270 top
R16 "10K" CR2012-0805 994,2164 r270 bottom
R17 "10K" CR2012-0805 994,2004 r270 top
R18 "10K" CR2012-0805 1094,994 r180 top
R19 "1.00K" CR2012-0805 865,1025 r180 bottom
R20 "1.00K" CR2012-0805 865,945 r0 bottom
R21 "1.00K" CR2012-0805 865,865 r0 bottom
R22 "7.15K" CR2012-0805 1094,1094 r0 top
R23 "10K" CR2012-0805 700,1675 r90 bottom
R24 "10K" CR2012-0805 600,1675 r270 bottom
R25 "10K" CR2012-0805 914,2164 r270 bottom
R26 "10K" CR2012-0805 834,2004 r270 top
R27 "30K" CR2012-0805 1074,1684 r270 top
R28 "330" CR2012-0805 3094.8,1559.84 r0 top
R29 "100" CR2012-0805 2554.8,1599.84 r180 bottom
R30 "100" CR2012-0805 2394.8,1599.84 r180 bottom
R31 "330" CR2012-0805 2374.8,1959.84 r0 bottom
R32 "Resistor Array" RES8-0.8 2574.8,1919.84 r90 bottom
R33 "Resistor Array" RES8-0.8 2775,765 r0 top
R34 "Resistor Array" RES8-0.8 2090.91,4190.54 r90 bottom
R35 "4.7K" CR2012-0805 2539.37,2893.69 r270 top
R36 "100" CR2012-0805 1140,580 r90 bottom
R37 "51.1K" CR2012-0805 602,5370 r0 bottom
R38 "1.21K" CR2012-0805 285,5615 r0 bottom
R39 "7.15K" CR2012-0805 950,2725 r0 top
R40 "1.00K" CR2012-0805 800,2725 r180 top
S1 "B3SN-3112P" SW_SMD_6MM 2937.32,1442 r0 top
S2 "SW DIP-8" DIP_SW_8WAY_SMD 1425,5025 r0 top
TP1 "Testpoint" TP1#1 1100,800 r90 top
TP2 "Testpoint" TP1#1 300,800 r90 top
TP3 "Testpoint" TP1#2 2570,4100 r0 top
TP4 "Testpoint" TP1#1 900,4500 r90 top
TP5 "Testpoint" TP1#1 1100,4500 r90 top
TP6 "Testpoint" TP1#1 2455,2156 r90 top
TP7 "Testpoint" TP1#1 1100,2700 r180 top
TP8 "Testpoint" TP1#3 712,4507 r0 top
TP9 "Testpoint" TP1#2 375,2700 r90 top
TP10 "Testpoint" TP1#2 1300,4500 r0 top
U1 "XC3S1600E-4FG320C" FG320 2086.63,3385.83 r180 top locked
U2 "SN74LVC2G34" SO-G6/E2.4 2903,1041 r0 top
U3 "ADR425BR" SO-G8 225,1350 r0 top
U4 "SN65LVDS100D" SO-G8 1790,1940 r0 top
U5 "OP284ES" SO-G8 225,1675 r0 top
U6 "SN65LVDT14" TSSO6x6-G20/D6.6 250,2275 r180 top
U7 "AD7685" TSSO3x5-G10 200,1975 r0 top
U8 "SN65LVDT101D" SO-G8 1530,1940 r180 top
U9 "74LVC74D" SO-G14 694,2284 r90 top
U10 "67.108864 MHz" VECTRON_C5310 800,250 r180 top
U11 "OP284ES" SO-G8 1014,1274 r270 top
U12 "SN74LVC1G00" SO-G5/E2.4 974,2184 r180 top
U13 "XCF08PVOG48C" VOG48 2454.8,1399.84 r180 top
U14 "SN74LVC541APW" PW020 2588.78,717.99 r0 top
U15 "LT1963A" TO-263 2799,4875 r0 top
U16 "SN65LVDT2" SO-G5/E2.4 1225,5400 r270 top
U17 "PTH08T240W" PTH08T240W 882,5370 r180 top
U18 "LT1963A-2.5" TO-263 2139,4875 r0 top
U19 "LT1763-1.8" SO-G8 3158,2040 r270 top
U20 "LT1763" SO-G8 900,2900 r90 top

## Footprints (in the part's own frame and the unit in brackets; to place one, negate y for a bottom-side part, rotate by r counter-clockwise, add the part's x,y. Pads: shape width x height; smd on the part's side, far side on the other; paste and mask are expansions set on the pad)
2MM_HDR2X7 [mm] "Connector; 2mm Header; 7x2 Position"
  rect 1.5x1.5 hole 0.9: 1(0,0)
  round 1.5 hole 0.9: 2(0,2) 3(2,0) 4(2,2) 5(4,0) 6(4,2) 7(6,0) 8(6,2) 9(8,0) 10(8,2) 11(10,0) 12(10,2) 13(12,0) 14(12,2)
  silkscreen extent -1.27,-1.27 13.25,3.25
918510x323 [mm] "Connector; IDC, Low Profile Male Header, Thru-Hole; 10 Position; Right Angle; Pitch 2.54 mm; Body 20.32 x 8.9 x 9.2 mm (LxWxH)"
  rect 1.65x1.65 hole 1: 1(-5.08,-2.54)
  round 1.65 hole 1: 2(-5.08,0) 3(-2.54,-2.54) 4(-2.54,0) 5(0,-2.54) 6(0,0) 7(2.54,-2.54) 8(2.54,0) 9(5.08,-2.54) 10(5.08,0)
  silkscreen extent -10.16,0 10.16,5.08
Bracket-RA_7774 [mil] "Keystone Electronics right-angle 4-40 steel, 7774"
  round 100 hole 62: 0(-100,107) 0(-100,-107) 0(100,107) 0(100,-107)
  silkscreen extent -125,-130 125,200
CA053035 [mil] "Axial film capacitor, Size 0.53\"(L) x 0.35\"(D)"
  round 65 hole 38: 1(0,0) 2(730,0)
  silkscreen extent 40,-175 690,175
CC1005-0402 [mm] "Chip Capacitor; Body 1.0 x 0.5 mm (LxW typ)"
  rect 0.9x0.7 smd: 1(-0.65,0) 2(0.65,0)
  silkscreen extent -1.4,-0.25 -1.4,0.25
CC1608-0603 [mm] "Chip Capacitor; Body 1.6 x 0.8 mm (LxW typ)"
  rect 1.1x1 smd: 1(-0.85,0) 2(0.85,0)
  silkscreen extent -1.7,-0.4 -1.7,0.4
CC2013-0805 [mm] "Chip Capacitor; Body 2.0 x 1.3 mm (LxW typ)"
  rect 1.15x1.4 smd: 1(-0.975,0) 2(0.975,0)
  silkscreen extent -1.85,-0.6 -1.85,0.6
CC3216-1206 [mm] "Chip Capacitor; Body 3.2 x 1.6 mm (LxW typ)"
  rect 1.6x1.8 smd: 1(-1.4,0) 2(1.4,0)
  silkscreen extent -0.3,-0.8 0.3,0.8
CL1608-0603 [mm] "Chip Inductor; Body 1.6 x 0.8 mm (LxW typ)"
  rect 1.1x1 smd: 1(-0.85,0) 2(0.85,0)
  silkscreen extent -1.7,-0.4 -1.7,0.4
CL2520-1008 [mm] "Chip Inductor; Body 2.54 x 2.0 mm (LxW typ)"
  rect 1.3x1.6 smd: 1(-1.3,0) 2(1.3,0)
  silkscreen extent -2.25,-0.7 -2.25,0.7
CR2012-0805 [mm] "Chip Resistor; Body 2.0 x 1.3 mm (LxW typ)"
  rect 1.3x1.5 smd: 1(-0.95,0) 2(0.95,0)
DIP_SW_8WAY_SMD [mm] "DIP Switch; 16 Leads"
  rect 1.2x2.6 smd: 1(-8.89,-4.45) 2(-6.35,-4.45) 3(-3.81,-4.45) 4(-1.27,-4.45) 5(1.27,-4.45) 6(3.81,-4.45) 7(6.35,-4.45) 8(8.89,-4.45) 9(8.89,4.45) 10(6.35,4.45) 11(3.81,4.45) 12(1.27,4.45) 13(-1.27,4.45) 14(-3.81,4.45) 15(-6.35,4.45) 16(-8.89,4.45)
  silkscreen extent -10.29,-2.5 10.31,2.5
FG320 [mm] "BGA, 320-Leads, Body 19x19mm, Pitch 1mm"
  round 0.5 smd: A1(-8.5,8.5) A2(-7.5,8.5) A3(-6.5,8.5) A4(-5.5,8.5) A5(-4.5,8.5) A6(-3.5,8.5) A7(-2.5,8.5) A8(-1.5,8.5) A9(-0.5,8.5) A10(0.5,8.5) A11(1.5,8.5) A12(2.5,8.5) A13(3.5,8.5) A14(4.5,8.5) A15(5.5,8.5) A16(6.5,8.5) A17(7.5,8.5) A18(8.5,8.5) B1(-8.5,7.5) B2(-7.5,7.5) B3(-6.5,7.5) B4(-5.5,7.5) B5(-4.5,7.5) B6(-3.5,7.5) B7(-2.5,7.5) B8(-1.5,7.5) B9(-0.5,7.5) B10(0.5,7.5) B11(1.5,7.5) B12(2.5,7.5) B13(3.5,7.5) B14(4.5,7.5) B15(5.5,7.5) B16(6.5,7.5) B17(7.5,7.5) B18(8.5,7.5) C1(-8.5,6.5) C2(-7.5,6.5) C3(-6.5,6.5) C4(-5.5,6.5) C5(-4.5,6.5) C6(-3.5,6.5) C7(-2.5,6.5) C8(-1.5,6.5) C9(-0.5,6.5) C10(0.5,6.5) C11(1.5,6.5) C12(2.5,6.5) C13(3.5,6.5) C14(4.5,6.5) C15(5.5,6.5) C16(6.5,6.5) C17(7.5,6.5) C18(8.5,6.5) D1(-8.5,5.5) D2(-7.5,5.5) D3(-6.5,5.5) D4(-5.5,5.5) D5(-4.5,5.5) D6(-3.5,5.5) D7(-2.5,5.5) D8(-1.5,5.5) D9(-0.5,5.5) D10(0.5,5.5) D11(1.5,5.5) D12(2.5,5.5) D13(3.5,5.5) D14(4.5,5.5) D15(5.5,5.5) D16(6.5,5.5) D17(7.5,5.5) D18(8.5,5.5) E1(-8.5,4.5) E2(-7.5,4.5) E3(-6.5,4.5) E4(-5.5,4.5) E5(-4.5,4.5) E6(-3.5,4.5) E7(-2.5,4.5) E8(-1.5,4.5) E9(-0.5,4.5) E10(0.5,4.5) E11(1.5,4.5) E12(2.5,4.5) E13(3.5,4.5) E14(4.5,4.5) E15(5.5,4.5) E16(6.5,4.5) E17(7.5,4.5) E18(8.5,4.5) F1(-8.5,3.5) F2(-7.5,3.5) F3(-6.5,3.5) F4(-5.5,3.5) F5(-4.5,3.5) F6(-3.5,3.5) F7(-2.5,3.5) F8(-1.5,3.5) F9(-0.5,3.5) F10(0.5,3.5) F11(1.5,3.5) F12(2.5,3.5) F13(3.5,3.5) F14(4.5,3.5) F15(5.5,3.5) F16(6.5,3.5) F17(7.5,3.5) F18(8.5,3.5) G1(-8.5,2.5) G2(-7.5,2.5) G3(-6.5,2.5) G4(-5.5,2.5) G5(-4.5,2.5) G6(-3.5,2.5) G7(-2.5,2.5) G8(-1.5,2.5) G9(-0.5,2.5) G10(0.5,2.5) G11(1.5,2.5) G12(2.5,2.5) G13(3.5,2.5) G14(4.5,2.5) G15(5.5,2.5) G16(6.5,2.5) G17(7.5,2.5) G18(8.5,2.5) H1(-8.5,1.5) H2(-7.5,1.5) H3(-6.5,1.5) H4(-5.5,1.5) H5(-4.5,1.5) H6(-3.5,1.5) H7(-2.5,1.5) H8(-1.5,1.5) H9(-0.5,1.5) H10(0.5,1.5) H11(1.5,1.5) H12(2.5,1.5) H13(3.5,1.5) H14(4.5,1.5) H15(5.5,1.5) H16(6.5,1.5) H17(7.5,1.5) H18(8.5,1.5) J1(-8.5,0.5) J2(-7.5,0.5) J3(-6.5,0.5) J4(-5.5,0.5) J5(-4.5,0.5) J6(-3.5,0.5) J7(-2.5,0.5) J8(-1.5,0.5) J11(1.5,0.5) J12(2.5,0.5) J13(3.5,0.5) J14(4.5,0.5) J15(5.5,0.5) J16(6.5,0.5) J17(7.5,0.5) J18(8.5,0.5) K1(-8.5,-0.5) K2(-7.5,-0.5) K3(-6.5,-0.5) K4(-5.5,-0.5) K5(-4.5,-0.5) K6(-3.5,-0.5) K7(-2.5,-0.5) K8(-1.5,-0.5) K11(1.5,-0.5) K12(2.5,-0.5) K13(3.5,-0.5) K14(4.5,-0.5) K15(5.5,-0.5) K16(6.5,-0.5) K17(7.5,-0.5) K18(8.5,-0.5) L1(-8.5,-1.5) L2(-7.5,-1.5) L3(-6.5,-1.5) L4(-5.5,-1.5) L5(-4.5,-1.5) L6(-3.5,-1.5) L7(-2.5,-1.5) L8(-1.5,-1.5) L9(-0.5,-1.5) L10(0.5,-1.5) L11(1.5,-1.5) L12(2.5,-1.5) L13(3.5,-1.5) L14(4.5,-1.5) L15(5.5,-1.5) L16(6.5,-1.5) L17(7.5,-1.5) L18(8.5,-1.5) M1(-8.5,-2.5) M2(-7.5,-2.5) M3(-6.5,-2.5) M4(-5.5,-2.5) M5(-4.5,-2.5) M6(-3.5,-2.5) M7(-2.5,-2.5) M8(-1.5,-2.5) M9(-0.5,-2.5) M10(0.5,-2.5) M11(1.5,-2.5) M12(2.5,-2.5) M13(3.5,-2.5) M14(4.5,-2.5) M15(5.5,-2.5) M16(6.5,-2.5) M17(7.5,-2.5) M18(8.5,-2.5) N1(-8.5,-3.5) N2(-7.5,-3.5) N3(-6.5,-3.5) N4(-5.5,-3.5) N5(-4.5,-3.5) N6(-3.5,-3.5) N7(-2.5,-3.5) N8(-1.5,-3.5) N9(-0.5,-3.5) N10(0.5,-3.5) N11(1.5,-3.5) N12(2.5,-3.5) N13(3.5,-3.5) N14(4.5,-3.5) N15(5.5,-3.5) N16(6.5,-3.5) N17(7.5,-3.5) N18(8.5,-3.5) P1(-8.5,-4.5) P2(-7.5,-4.5) P3(-6.5,-4.5) P4(-5.5,-4.5) P5(-4.5,-4.5) P6(-3.5,-4.5) P7(-2.5,-4.5) P8(-1.5,-4.5) P9(-0.5,-4.5) P10(0.5,-4.5) P11(1.5,-4.5) P12(2.5,-4.5) P13(3.5,-4.5) P14(4.5,-4.5) P15(5.5,-4.5) P16(6.5,-4.5) P17(7.5,-4.5) P18(8.5,-4.5) R1(-8.5,-5.5) R2(-7.5,-5.5) R3(-6.5,-5.5) R4(-5.5,-5.5) R5(-4.5,-5.5) R6(-3.5,-5.5) R7(-2.5,-5.5) R8(-1.5,-5.5) R9(-0.5,-5.5) R10(0.5,-5.5) R11(1.5,-5.5) R12(2.5,-5.5) R13(3.5,-5.5) R14(4.5,-5.5) R15(5.5,-5.5) R16(6.5,-5.5) R17(7.5,-5.5) R18(8.5,-5.5) T1(-8.5,-6.5) T2(-7.5,-6.5) T3(-6.5,-6.5) T4(-5.5,-6.5) T5(-4.5,-6.5) T6(-3.5,-6.5) T7(-2.5,-6.5) T8(-1.5,-6.5) T9(-0.5,-6.5) T10(0.5,-6.5) T11(1.5,-6.5) T12(2.5,-6.5) T13(3.5,-6.5) T14(4.5,-6.5) T15(5.5,-6.5) T16(6.5,-6.5) T17(7.5,-6.5) T18(8.5,-6.5) U1(-8.5,-7.5) U2(-7.5,-7.5) U3(-6.5,-7.5) U4(-5.5,-7.5) U5(-4.5,-7.5) U6(-3.5,-7.5) U7(-2.5,-7.5) U8(-1.5,-7.5) U9(-0.5,-7.5) U10(0.5,-7.5) U11(1.5,-7.5) U12(2.5,-7.5) U13(3.5,-7.5) U14(4.5,-7.5) U15(5.5,-7.5) U16(6.5,-7.5) U17(7.5,-7.5) U18(8.5,-7.5) V1(-8.5,-8.5) V2(-7.5,-8.5) V3(-6.5,-8.5) V4(-5.5,-8.5) V5(-4.5,-8.5) V6(-3.5,-8.5) V7(-2.5,-8.5) V8(-1.5,-8.5) V9(-0.5,-8.5) V10(0.5,-8.5) V11(1.5,-8.5) V12(2.5,-8.5) V13(3.5,-8.5) V14(4.5,-8.5) V15(5.5,-8.5) V16(6.5,-8.5) V17(7.5,-8.5) V18(8.5,-8.5)
  silkscreen extent -10.27,-9.5 9.5,9.5, body extent -9.5,-9.5 9.5,9.5, height 2
HDR1X2 [mil] "Connector; Header; 2 Position"
  rect 62x62 hole 40: 1(0,0)
  round 62 hole 40: 2(100,0)
  silkscreen extent -50,-50 150,50
HDR2X8 [mm] "Connector; Header; 8x2 Position"
  rect 1.5x1.5 hole 0.9: 1(0,0)
  round 1.5 hole 0.9: 2(0,2.54) 3(2.54,0) 4(2.54,2.54) 5(5.08,0) 6(5.08,2.54) 7(7.62,0) 8(7.62,2.54) 9(10.16,0) 10(10.16,2.54) 11(12.7,0) 12(12.7,2.54) 13(15.24,0) 14(15.24,2.54) 15(17.78,0) 16(17.78,2.54)
  silkscreen extent -1.27,-1.27 19.05,3.81
LED-2 [mil] "Rectangular right angle LED"
  round 120 hole 100: 0(0,-220)
  round 62 hole 32: 1(0,100) 2(0,0)
  silkscreen extent -65,-295 65,175
LED-0805 [mm] "SMD LED, 805, Body 2.0 x 1.3 mm (LxW typ)"
  rect 1.15x1.4 smd: 1(-0.975,0) 2(0.975,0)
  silkscreen extent -1.85,-0.6 -1.85,0.6
LIGO_LOGO [mil] "LIGO logo"
  silkscreen extent 3,-402 511,-3
MSA/SFP2x10 [mm] "Multi Source Agreement, Small Factor Plugable"
  rect 2x0.5 smd: 1(0,0) 2(0,-0.8) 3(0,-1.6) 4(0,-2.4) 5(0,-3.2) 6(0,-4) 7(0,-4.8) 8(0,-5.6) 9(0,-6.4) 10(0,-7.2) 11(8.2,-6.8) 12(8.2,-6) 13(8.2,-5.2) 14(8.2,-4.4) 15(8.2,-3.6) 16(8.2,-2.8) 17(8.2,-2) 18(8.2,-1.2) 19(8.2,-0.4) 20(8.2,0.4)
  rect 1.8x1.8 hole 1.041: 21(-26.8,-4.85) 21(-26.8,3.73) 21(-21.8,-10.53) 21(-16.8,3.73) 21(-11.8,-10.53) 21(-6.8,-7.35) 21(-6.8,-1.95) 21(-6.8,3.73) 21(-1.8,-10.53) 21(8.2,-10.53)
  round 1.4 hole 0.95: 22(-4,3.73) 22(-4,-10.53) 22(0.7,3.73) 22(0.7,-10.53) 22(5.7,3.73) 22(5.7,-10.53) 22(10.3,-8.2) 22(10.3,-3.4) 22(10.3,1.4)
  round 2 hole 1.575: 23(4.2,1.4) 23(4.2,-8.2)
  round 1.3 hole 0.85: 24(3.2,3.73)
  silkscreen extent -31.2,-11.43 10.9,4.63
MVR1251 [mil] "Power Inductor, MVR series, Coilcraft"
  rect 100x375 smd: 1(-155.5,0) 2(155.5,0)
  silkscreen extent -80,-230 80,230
PTH08T240W [mil] "Power Module, T2 turbo trans series, 11 pin"
  round 85 smd: 1(0,0) 2(0,-125) 3(0,-500) 4(125,-500) 5(500,-500) 6(750,-500) 7(750,-375) 8(750,-250) 9(750,-125) 10(750,0) 11(125,0)
  silkscreen extent -140,-580 830,80
PW020 [mm] "Shrink Small Outline; 20 Leads; Body Width 4.4 mm; Pitch 0.65 mm"
  rect 0.3x1.65 smd: 1(-2.925,-2.775) 2(-2.275,-2.775) 3(-1.625,-2.775) 4(-0.975,-2.775) 5(-0.325,-2.775) 6(0.325,-2.775) 7(0.975,-2.775) 8(1.625,-2.775) 9(2.275,-2.775) 10(2.925,-2.775) 11(2.925,2.775) 12(2.275,2.775) 13(1.625,2.775) 14(0.975,2.775) 15(0.325,2.775) 16(-0.325,2.775) 17(-0.975,2.775) 18(-1.625,2.775) 19(-2.275,2.775) 20(-2.925,2.775)
  silkscreen extent -3.75,-2.9 3.3,1.55
QSE040 [mil] "Samtec hi-speed socket, 0.8mm, QSE series, 80 pins"
  rect 16x89 smd: 1(-692.9,-112.78) 2(-692.9,112.78) 3(-661.42,-112.78) 4(-661.42,112.78) 5(-629.92,-112.78) 6(-629.92,112.78) 7(-598.42,-112.78) 8(-598.42,112.78) 9(-566.92,-112.78) 10(-566.92,112.78) 11(-535.42,-112.78) 12(-535.42,112.78) 13(-503.93,-112.78) 14(-503.93,112.78) 15(-472.43,-112.78) 16(-472.43,112.78) 17(-440.93,-112.78) 18(-440.93,112.78) 19(-409.43,-112.78) 20(-409.43,112.78) 21(-377.95,-112.78) 22(-377.95,112.78) 23(-346.45,-112.78) 24(-346.45,112.78) 25(-314.95,-112.78) 26(-314.95,112.78) 27(-283.45,-112.78) 28(-283.45,112.78) 29(-251.97,-112.78) 30(-251.97,112.78) 31(-220.47,-112.78) 32(-220.47,112.78) 33(-188.97,-112.78) 34(-188.97,112.78) 35(-157.47,-112.78) 36(-157.47,112.78) 37(-125.98,-112.78) 38(-125.98,112.78) 39(-94.48,-112.78) 40(-94.48,112.78) 41(94.48,-112.78) 42(94.48,112.78) 43(125.98,-112.78) 44(125.98,112.78) 45(157.47,-112.78) 46(157.47,112.78) 47(188.97,-112.78) 48(188.97,112.78) 49(220.47,-112.78) 50(220.47,112.78) 51(251.97,-112.78) 52(251.97,112.78) 53(283.45,-112.78) 54(283.45,112.78) 55(314.95,-112.78) 56(314.95,112.78) 57(346.45,-112.78) 58(346.45,112.78) 59(377.95,-112.78) 60(377.95,112.78) 61(409.43,-112.78) 62(409.43,112.78) 63(440.93,-112.78) 64(440.93,112.78) 65(472.43,-112.78) 66(472.43,112.78) 67(503.93,-112.78) 68(503.93,112.78) 69(535.42,-112.78) 70(535.42,112.78) 71(566.92,-112.78) 72(566.92,112.78) 73(598.42,-112.78) 74(598.42,112.78) 75(629.92,-112.78) 76(629.92,112.78) 77(661.42,-112.78) 78(661.42,112.78) 79(692.9,-112.78) 80(692.9,112.78)
  rect 109x16 smd: 81(-711.22,0) 84(-76.17,0) 85(76.17,0) 88(711.22,0)
  rect 185x16 smd: 82(-518.7,0) 83(-268.7,0) 86(268.7,0) 87(518.7,0)
  round 40 / inner round 60 / far side round 60 hole 40 mask+50: 89(-789.95,104.92) 90(789.95,104.92)
  silkscreen extent -821,-205 821,167
RES4-0.8 [mm] "Resistor chip array, 0.8mm spacing, 1.6mm wide, 4 pads"
  rect 0.9x0.5 smd: 1(0,0) 2(0,-0.8) 3(1.6,-0.8) 4(1.6,0)
  silkscreen extent 0.6,-1.2 1,0.4
RES8-0.8 [mm] "Resistor chip array, 0.8mm spacing, 1.6mm wide, 8 pads"
  rect 0.9x0.5 smd: 1(0,0) 2(0,-0.8) 3(0,-1.6) 4(0,-2.4) 5(1.6,-2.4) 6(1.6,-1.6) 7(1.6,-0.8) 8(1.6,0)
  silkscreen extent 0.6,-2.7 1,0.4
SO-G3/C2.25 [mm] "SOT-23; 3 Leads; Body 3.0 x 2.5 mm, inc. leads (LxW max)"
  rect 0.95x1 smd: 1(-0.95,-1.125) 2(0.95,-1.125) 3(0,1.125)
  silkscreen extent -2.1,-1.25 1.32,1.13
SO-G5/E2.4 [mm] "Small Outline; 5 Leads; Body 3.6 x 3.6 mm, inc. leads (LxW max)"
  rect 0.55x1.45 smd: 1(-0.95,-1.35) 2(0,-1.35) 3(0.95,-1.35) 4(0.95,1.35) 5(-0.95,1.35)
  silkscreen extent -1.68,-2.52 1.55,1.2
SO-G6/E2.4 [mm] "Small Outline; 6 Leads; Body 3.6 x 3.6 mm, inc. leads (LxW max)"
  rect 0.55x1.45 smd: 1(-0.95,-1.35) 2(0,-1.35) 3(0.95,-1.35) 4(0.95,1.35) 5(0,1.35) 6(-0.95,1.35)
  silkscreen extent -1.67,-2.52 1.55,1.2
SO-G8 [mm] "Small Outline; 8 Leads; Body Width 3.9 mm; Pitch 1.27 mm"
  rect 0.6x2.2 smd: 1(-1.905,-2.6) 2(-0.635,-2.6) 3(0.635,-2.6) 4(1.905,-2.6) 5(1.905,2.6) 6(0.635,2.6) 7(-0.635,2.6) 8(-1.905,2.6)
  silkscreen extent -2.88,-2.72 2.5,1.1
SO-G14 [mm] "Small Outline; 14 Leads; Body Width 4 mm; Pitch 1.27 mm"
  rect 0.6x2.2 smd: 1(-3.81,-2.6) 2(-2.54,-2.6) 3(-1.27,-2.6) 4(0,-2.6) 5(1.27,-2.6) 6(2.54,-2.6) 7(3.81,-2.6) 8(3.81,2.6) 9(2.54,2.6) 10(1.27,2.6) 11(0,2.6) 12(-1.27,2.6) 13(-2.54,2.6) 14(-3.81,2.6)
  silkscreen extent -4.78,-2.72 4.37,1.1
SW_SMD_6MM [mm]
  rect 2.75x1.4 smd: 1(0,0) 2(6.8,0) 3(0,-4) 4(6.8,-4) 5(0,-2)
  silkscreen extent -2.75,-5 6.38,1
TBLOCK-5.08-2 [mil] "Terminal Block, 5.08mm, 2pin"
  rect 100x100 hole 62: 1(-100,0)
  round 100 hole 62: 2(100,0)
  silkscreen extent -200,-160 200,160
TC7343-2917 [mm]
  rect 2.6x2.4 smd: 1(-3.2,0) 2(3.2,0)
  silkscreen extent -4.58,-2.3 3.8,2.42
TO-263 [mm] "D2-PAK; 5 Leads; Body 14.4 (inc. leads) x 10.4 mm (LxW max)"
  rect 1.05x2.1 smd: 1(-3.4,-4.225) 2(-1.7,-4.225) 3(0,-4.225) 4(1.7,-4.225) 5(3.4,-4.225)
  rect 10.5x10.3 smd: 3(0,4.225)
  silkscreen extent -5.55,-5.85 5.55,9.28
TP1#1 [mil] "Testpoint pin"
  round 100 hole 62: 1(0,0)
TP1#2 [mil] "Testpoint pin"
  round 100 hole 62.2: 1(0,0)
TP1#3 [mil] "Testpoint pin"
  round 100 hole 62: 1(-12,-7)
TSSO3x5-G10 [mm] "Shrink Small Outline; 10 Leads; Body Width 3 mm; Pitch 0.5 mm"
  rect 0.3x1.6 smd: 1(-1,-2.05) 2(-0.5,-2.05) 3(0,-2.05) 4(0.5,-2.05) 5(1,-2.05) 6(1,2.05) 7(0.5,2.05) 8(0,2.05) 9(-0.5,2.05) 10(-1,2.05)
  silkscreen extent -1.82,-2.17 1.58,0.85
TSSO6x6-G20/D6.6 [mm] "Shrink Small Outline; 20 Leads; Body Width 4.4 mm; Pitch 0.65 mm"
  rect 0.3x1.6 smd: 1(-2.925,-2.85) 2(-2.275,-2.85) 3(-1.625,-2.85) 4(-0.975,-2.85) 5(-0.325,-2.85) 6(0.325,-2.85) 7(0.975,-2.85) 8(1.625,-2.85) 9(2.275,-2.85) 10(2.925,-2.85) 11(2.925,2.85) 12(2.275,2.85) 13(1.625,2.85) 14(0.975,2.85) 15(0.325,2.85) 16(-0.325,2.85) 17(-0.975,2.85) 18(-1.625,2.85) 19(-2.275,2.85) 20(-2.925,2.85)
  silkscreen extent -3.75,-2.97 3.3,1.65
VECTRON_C5310 [mm] "Vectron VCXO, C5310 series"
  rect 3x1.3 smd: 1(0,0) 2(0,-2.54) 3(0,-5.08) 4(8.7,-5.08) 5(8.7,-2.54) 6(8.7,0)
  silkscreen extent -2.29,-9.75 9.25,4.75
VOG48 [mm] "48-Pin Thin Small Outline Package 0.5 mm Pitch (VOG48) - Pb-Free"
  rect 0.3x1.6 smd: 1(-5.75,-9.6) 2(-5.25,-9.6) 3(-4.75,-9.6) 4(-4.25,-9.6) 5(-3.75,-9.6) 6(-3.25,-9.6) 7(-2.75,-9.6) 8(-2.25,-9.6) 9(-1.75,-9.6) 10(-1.25,-9.6) 11(-0.75,-9.6) 12(-0.25,-9.6) 13(0.25,-9.6) 14(0.75,-9.6) 15(1.25,-9.6) 16(1.75,-9.6) 17(2.25,-9.6) 18(2.75,-9.6) 19(3.25,-9.6) 20(3.75,-9.6) 21(4.25,-9.6) 22(4.75,-9.6) 23(5.25,-9.6) 24(5.75,-9.6) 25(5.75,9.6) 26(5.25,9.6) 27(4.75,9.6) 28(4.25,9.6) 29(3.75,9.6) 30(3.25,9.6) 31(2.75,9.6) 32(2.25,9.6) 33(1.75,9.6) 34(1.25,9.6) 35(0.75,9.6) 36(0.25,9.6) 37(-0.25,9.6) 38(-0.75,9.6) 39(-1.25,9.6) 40(-1.75,9.6) 41(-2.25,9.6) 42(-2.75,9.6) 43(-3.25,9.6) 44(-3.75,9.6) 45(-4.25,9.6) 46(-4.75,9.6) 47(-5.25,9.6) 48(-5.75,9.6)
  silkscreen extent -6.57,-9.72 6.05,8.4

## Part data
B1 B2: library part Bracket_7774, "Keystone Electronics right-angle 4-40 steel, 7774"
C1 C2 C3 C4 C5 C6 C7 C8 C9 C10 C11 C12 C13 C14 C15 C17 C18 C19 C20 C21 C22 C23 C24 C25 C26 C27 C28 C29 C30 C31 C32 C33 C34 C35 C36 C37 C38 C39 C40 C42 C43 C48 C49 C50 C55 C56 C58 C59 C60 C61 C62 C65 C66 C67 C68 C69 C70 C71 C72 C73 C74 C75 C76 C77 C78 C79 C80 C81 C82 C83 C84 C85 C86 C87 C88 C89 C90 C91 C92 C93 C94 C95 C96 C97 C98 C99 C100 C101 C102 C103 C104 C105 C106 C107 C108 C109 C110 C111 C112 C113 C114 C115 C116 C117 C118 C119 C120 C121 C122 C123 C124 C125 C126 C127 C128 C129 C130 C131 C132 C133 C134 C135 C136: library part ChipCap, "Capacitor, surface mount"
C16: library part CapFilmAxial, "Film Capacitor, axial lead"
C41 C44 C45 C46 C47 C51 C52 C53 C54 C57 C63 C64: library part ChipTantalum, "Tantalum capacitor, surface mount"
DS1 DS2 DS3: "Panel mount LED"
FR1: library part BLM31PG121SN1, "ferrite bead, 22Ohm at 100MHz, 603"
J1: "fiber optic transceiver, 1.25GB/s, MM, LC, SFP"
L1 L2: library part ChipInductor, "Inductor"
L3: library part MVR1251, "Power inductor. MVR series"
LOGO1: library part LIGO_logo
P1 P2: library part SAMTEC_QSE40, "Samtec hi-speed socket, 0.8mm, 80 pins"
P3: "Header, 8-Pin, Dual row"
P4: "Header, 2-Pin"
P5: "Flat Cable Connector (IDC), Low-Profile Male Header, Angled Solder Pin, 10 Contacts, Performance Level 2"
P6: library part Xilinx_JTAG_Header, "Xilinx JTAG header, 7-Pin, Dual row"
P7: "Terminal block, 5.08mm, 2-Pin"
Q1 Q2 Q3: "FDV301N, Digital FET, N-channel, SOT23"
R1 R2 R3 R4 R5 R8 R9 R10 R11 R12 R13 R14 R15 R16 R17 R18 R19 R20 R21 R22 R23 R24 R25 R26 R27 R28 R29 R30 R31 R35 R36 R37 R38 R39 R40: library part ChipRes1, "Resistor, surface mount"
R6 R32 R33 R34: library part RES4_ARRAY, "Resistor Network, parallel, 4 resistors"
R7: library part RES2_ARRAY, "Resistor Network, parallel, 2 resistors"
S1: "Switch, SMD, 6mm"
S2: "DIP Switch, 8 Position, SPST"
TP1 TP2: library part TP_SIGNAL, "Testpoint, yellow"
TP3 TP4 TP5 TP6 TP7 TP8: library part TP_POSITIVE, "Testpoint, red"
TP9 TP10: library part TP_GND, "Testpoint, black"
U1: "Spartan-3E 1.2V FPGA, 250 User I/Os, 320-Ball FBGA, Standard Performance, Commercial Grade"
U2: "Dual buffer"
U3: library part ADR292ER, "Low-Noise Micropower Precision Voltage Reference"
U4 U8: library part SN65LVDS100, "DIFF TRANSLATOR"
U5 U11: "Precision Rail-to-Rail Input and Output Operational Amplifier"
U7: "16 bit ADC, 250kSPS, pseudo differential, serial"
U9: library part 74F74PC, "Dual D-Type Positive Edge-Triggered Flip-Flop"
U10: library part VECTRON_C5310, "Voltage controlled crystal oscillator"
U13: "XCF00P Series, Platform Flash In-System Programmable Configuration 1.8V PROM, 48-Pin TSSOP, Pb-Free, 8-Megabit, Commercial Grade"
U14: library part SN74LVC541APWLE, "Octal Buffer/Driver with 3-State Outputs"
U15: "5 Terminal positive LDO regulator, 1.5A"
U16: library part SN65LVDT2DBV, "Single LVDS Receiver with 100 Ohm termination"
U17: "Adjustable power module, 10A, 4.5V to 14V input, non-isolated"
U18: library part LT1963A, "5 Terminal positive LDO regulator, 1.5A"
U19: library part LT1763, "Positive voltage regulator"
U20: "Positive voltage regulator"

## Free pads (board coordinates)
  round 190 hole 125: 0(200,2700) 0(200,4700) 0(3200,2700) 0(3200,4700)
  round 65 hole 38: 0(600,1880)
  round 250 hole 150: 0(1200,2300) 0(1200,5800) 0(3200,2300)

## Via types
v1: diameter 23, hole 12, Top Layer to Bottom Layer, 669 vias
v2: diameter 23, hole 12.01, Top Layer to Bottom Layer, 33 vias
v3: diameter 50, hole 28, Top Layer to Bottom Layer, 6 vias

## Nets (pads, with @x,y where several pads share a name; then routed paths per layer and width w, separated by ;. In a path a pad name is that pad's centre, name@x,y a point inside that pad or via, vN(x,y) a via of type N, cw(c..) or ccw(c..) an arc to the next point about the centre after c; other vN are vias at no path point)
12V: C49.1 C51.1 C52.1 C53.1 C62.2 C63.1 C64.1 L3.2 P2.77 P2.79 TP8.1 U17.2 U17.10 U20.5 U20.8 | length 4778.5
  Top Layer w8: U20.8@797.64,2825 855,2825 880,2850 880,2950 855,2975 U20.5@804,2975
  Top Layer w12: P2.77@412.78,4361.42 P2.79@412.78,4392.9 477.1,4392.9
  Top Layer w25: U17.10@132,5370 357,5370 482,5495 U17.2@882,5495 ; 477.1,4392.9 592.9,4392.9 TP8.1@700,4500 ; C64.1@650.98,4725 v1(731,4725) ; C62.2@663.39,2725 663.39,2812.4 675.98,2825 U20.8@797.64,2825 ; C63.1@711.02,4238 v1(787,4238)
  Bottom Layer w25: 700,4240 702,4238 v1(787,4238)
  Bottom Layer w50: v1(700,2825) 700,4700 975,4975 v1(975,5575)
  other v1: 975,5475 975,5525
ACLK_N: U1.E16 U6.6 | length 2337.5
  Top Layer w6: U6.6@237.2,2387.2 237.2,2414.84 244,2421.64 244,2450.97 325.03,2532 1455.03,2532 1498,2574.97 1498,3092.49 1574.8,3169.29 v1(1574.8,3188.98) ; U1.E16@1830.71,3208.66 v1(1850.39,3228.35)
  Mid-Layer 1 w6: v1(1574.8,3188.98) 1811.02,3188.98 v1(1850.39,3228.35)
ACLK_P: U1.E15 U6.5 | length 2287.4
  Top Layer w6: U6.5@262.8,2387.2 262.8,2414.84 256,2421.64 256,2446 330,2520 1460,2520 1510,2570 1510,3074.96 v1(1604.33,3169.29) ; v1(1850.41,3188.99) U1.E15@1870.1,3208.66
  Mid-Layer 1 w6: v1(1604.33,3169.29) 1830.71,3169.29 v1(1850.41,3188.99)
ACNV_N: U1.F14 U6.8 | length 2454.7
  Top Layer w6: U6.8@186.02,2387.2 186.02,2414.84 192.82,2421.64 192.82,2449.79 305.03,2562 1425.03,2562 1468,2604.97 1468,3101.86 1515.75,3149.61 v1(1515.75,3198.82) ; v1(1889.76,3228.35) U1.F14@1909.45,3248.03
  Mid-Layer 2 w6: v1(1515.75,3198.82) 1515.75,3208.66 1555.12,3248.03 1870.08,3248.03 v1(1889.76,3228.35)
ACNV_P: U1.F15 U6.7 | length 2398.8
  Top Layer w6: U6.7@211.61,2387.2 211.61,2414.84 204.82,2421.64 204.82,2444.82 310,2550 1430,2550 1480,2600 1480,3094.17 1535.43,3149.61 v1(1535.43,3169.29) ; v1(1850.39,3267.72) U1.F15@1870.1,3248.03
  Mid-Layer 1 w6: v1(1535.43,3169.29) 1535.43,3208.66 1574.8,3248.03 1830.71,3248.03 v1(1850.39,3267.72)
AGND: C2.2 C3.1 C5.1 C10.1 C13.2 C14.1 C15.1 C18.1 C20.2 C22.1 C23.1 C25.1 C61.2 P4.2 R21.2 R24.2 U3.4 U5.4 U7.4 U7.5 U10.3 U11.4 | length 1197.1
  Top Layer w8: v1(911.64,1166.64) U11.4@911.64,1199 ; C25.1@1154,1722.39 v1(1202.39,1722.39) ; v1(1187.39,1135.61) C22.1@1234,1135.61 ; v1(1190.61,1412.39) C18.1@1234,1412.39
  Top Layer w10: U7.4@219.68,1894.29 v2(265.71,1894.29)
  Top Layer w15: v1(1260,2705) C61.2@1260,2764.88
  Top Layer w20: v2(300,1190) U3.4@300,1247.64 ; v2(300,1515) U5.4@300,1572.64 ; U10.3@800,450 v2(880,450)
  Bottom Layer w15: v2(83.39,1636.61) C5.1@125,1636.61 ; v2(114.88,1405.12) C2.2@175,1405.12 ; C13.2@225,2013.39 v2(288.39,2013.39) ; C3.1@275,1311.61 275,1215 v2(300,1190) ; C10.1@325,1730.12 v2(379.88,1730.12) ; C23.1@500,1636.61 v2(546.61,1636.61) 547.6,1637.6 R24.2@600,1637.6 ; v1(902.4,737.6) R21.2@902.4,865
  Bottom Layer w20: C15.1@650.59,250 C14.1@650.59,312.2 ; C15.1@660,250 v2(701.61,250) ; C14.1@663.39,325 v2(705,325)
AIN_N: U1.G16 U6.10 | length 2459.5
  Top Layer w6: U6.10@134.84,2387.2 134.84,2414.84 141.64,2421.64 141.64,2448.61 285.03,2592 1395.03,2592 1438,2634.97 1438,3130.91 1476.38,3169.29 v1(1476.38,3198.82) ; v1(1811.04,3307.09) U1.G16@1830.73,3287.4
  Mid-Layer 2 w6: v1(1476.38,3198.82) 1476.38,3257.87 1505.91,3287.4 1614.17,3287.4 1633.86,3307.09 v1(1811.04,3307.09)
AIN_P: U1.G15 U6.9 | length 2476.6
  Top Layer w6: U6.9@160.43,2387.2 160.43,2414.84 153.64,2421.64 153.64,2443.64 290,2580 1400,2580 1450,2630 1450,3123.23 v1(1496.06,3169.29) ; v1(1850.39,3307.09) U1.G15@1870.1,3287.4
  Mid-Layer 2 w6: v1(1496.06,3169.29) 1496.06,3248.03 1515.75,3267.72 1614.17,3267.72 1633.86,3287.4 1830.71,3287.4 v1(1850.39,3307.09)
CCLK: R29.2 R30.1 U1.U16 U13.12 | length 2809.8
  Top Layer w6: v1(1811.02,3740.16) 1811.02,3700.8 U1.U16@1830.73,3681.1
  Top Layer w12: v1(2464.65,1695) U13.12@2464.65,1777.79
  MidLayer3 w6: v1(1811.02,3740.16) 2007.87,3740.16 2027.56,3720.47 2106.3,3720.47 2145.67,3681.1 2145.67,3051.18 2224.41,2972.44 2224.41,2421.26 2303.15,2342.52 2303.15,2214.57 2464.65,2053.07 v1(2464.65,1695)
  Bottom Layer w12: R30.1@2432.21,1599.84 R29.2@2517.4,1599.84 ; v1(2464.65,1695) 2464.65,1605 2469.8,1599.84
CFG_CLK: P1.79 U1.R5 | length 1733
  Top Layer w6: U1.R5@2263.8,3602.36 v1(2283.46,3622.06)
  Top Layer w12: P1.79@3212.78,4392.9 v1(3273.98,4392.9)
  Mid-Layer 1 w6: v1(2283.46,3622.06) 2322.85,3661.45 2322.85,3897.65 2342.52,3917.32 v1(2342.52,3966.54)
  Bottom Layer w6: v1(2342.52,3966.54) 2342.52,3976.38 2342.52,3996.06 2342.52,4251.52 2377,4286 2805,4286 2841,4322 3008,4322 3078.9,4392.9 v1(3273.98,4392.9)
CFG_CS: P1.80 U1.U5 | length 1455.6
  Top Layer w6: U1.U5@2263.8,3681.1 2283.46,3700.79 2283.46,3759.84 2322.83,3799.21 v1(2322.83,3937.01)
  Top Layer w12: P1.80@2987.22,4392.9 v1(3048.42,4392.9)
  Bottom Layer w6: v1(2322.83,3937.01) 2322.83,3976.38 2322.83,3996.06 2322.83,4277.83 2385,4340 2995.52,4340 v1(3048.42,4392.9)
CFG_SI: P1.77 U1.V2 | length 1424
  Top Layer w6: v1(2362.2,3937.01) 2362.22,3740.16 U1.V2@2381.91,3720.47
  Top Layer w12: v1(3151.58,4361.42) P1.77@3212.78,4361.42
  Bottom Layer w6: v1(2362.2,3937.01) 2362.2,3976.38 2362.2,3996.06 2362.2,4232.28 2401.57,4271.65 3031.5,4271.65 3121.26,4361.42 v1(3151.58,4361.42)
CFG_SO: P1.78 U1.T5 | length 1379
  Top Layer w6: U1.T5@2263.8,3641.73 v1(2283.46,3661.42)
  Top Layer w12: v1(2926.02,4361.42) P1.78@2987.22,4361.42
  Mid-Layer 1 w6: v1(2283.46,3661.42) 2303.15,3681.1 v1(2303.15,3964.57)
  Bottom Layer w6: v1(2303.15,3964.57) 2303.15,3976.38 2303.15,3996.06 2303.15,4291.34 2373.23,4361.42 v1(2926.02,4361.42)
CNTROUT_N: U1.D16 U6.4 | length 2220.4
  Top Layer w6: U6.4@288.39,2387.2 288.39,2414.84 295.18,2421.64 295.18,2452.15 345.03,2502 1485.03,2502 1528,2544.97 1528,3063.43 1633.86,3169.29 1712.6,3169.29 1732.28,3188.98 1811.01,3188.98 U1.D16@1830.71,3169.29
CNTROUT_P: U1.D17 U6.3 | length 2148.2
  Top Layer w6: U6.3@313.98,2387.2 313.98,2414.84 307.18,2421.64 307.18,2447.18 350,2490 1490,2490 1540,2540 1540,3055.75 1633.86,3149.61 1771.67,3149.61 U1.D17@1791.36,3169.29
D_IN: U1.N10 U13.28 | length 2648.8
  Top Layer w6: v1(2047.26,3543.31) U1.N10@2066.95,3523.62 ; v1(2287.32,1193.07) 2287.48,1192.91 U13.28@2287.48,1021.89
  MidLayer3 w6: v1(2047.26,3543.31) 2066.95,3523.62 2066.95,2972.44 2106.3,2933.09 2106.3,2401.57 2224.41,2283.46 2224.41,1255.98 v1(2287.32,1193.07)
DONE: Q3.1 R31.2 U1.V17 U13.13 | length 3078.1
  Top Layer w6: v1(1771.65,3740.16) U1.V17@1791.34,3720.47 ; v1(2412.21,1907.24) 2444.96,1874.49 2444.96,1675.04 2462,1658 v1(2511,1658) ; v1(2906.8,1680.84) Q3.1@2943.69,1680.84
  Mid-Layer 2 w6: v1(2511,1658) 2883.96,1658 v1(2906.8,1680.84)
  MidLayer3 w6: v1(1771.65,3740.16) 1830.71,3681.1 2066.93,3681.1 2106.3,3641.73 2106.3,3011.81 2204.72,2913.39 2204.72,2405.51 2283.46,2326.77 2283.46,2204.72 2412.21,2075.98 v1(2412.21,1907.24)
  Bottom Layer w8: v1(2412.21,1907.24) R31.2@2412.21,1959.84
FAIL: Q1.1 R4.2 U1.R9 | length 2658.4
  Top Layer w6: U1.R9@2106.32,3602.36 v1(2126,3622.05)
  Bottom Layer w6: v1(2126,3622.05) 2145.67,3641.72 2145.67,4251.97 2283.46,4389.76 2996.26,4389.76 3075,4468.5
  Bottom Layer w8: 3075,4468.5 3075,4775 3125,4825 3125,5287.4 R4.2@3087.4,5325 Q1.1@3087.4,5405.71
FAULT: J1.2 R6.4 | length 205.4
  Top Layer w8: v1(1561.5,1181.5) J1.2@1561.5,1240
  Bottom Layer w8: v1(1561.5,1181.5) 1561.5,1231.5 R6.4@1630,1300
